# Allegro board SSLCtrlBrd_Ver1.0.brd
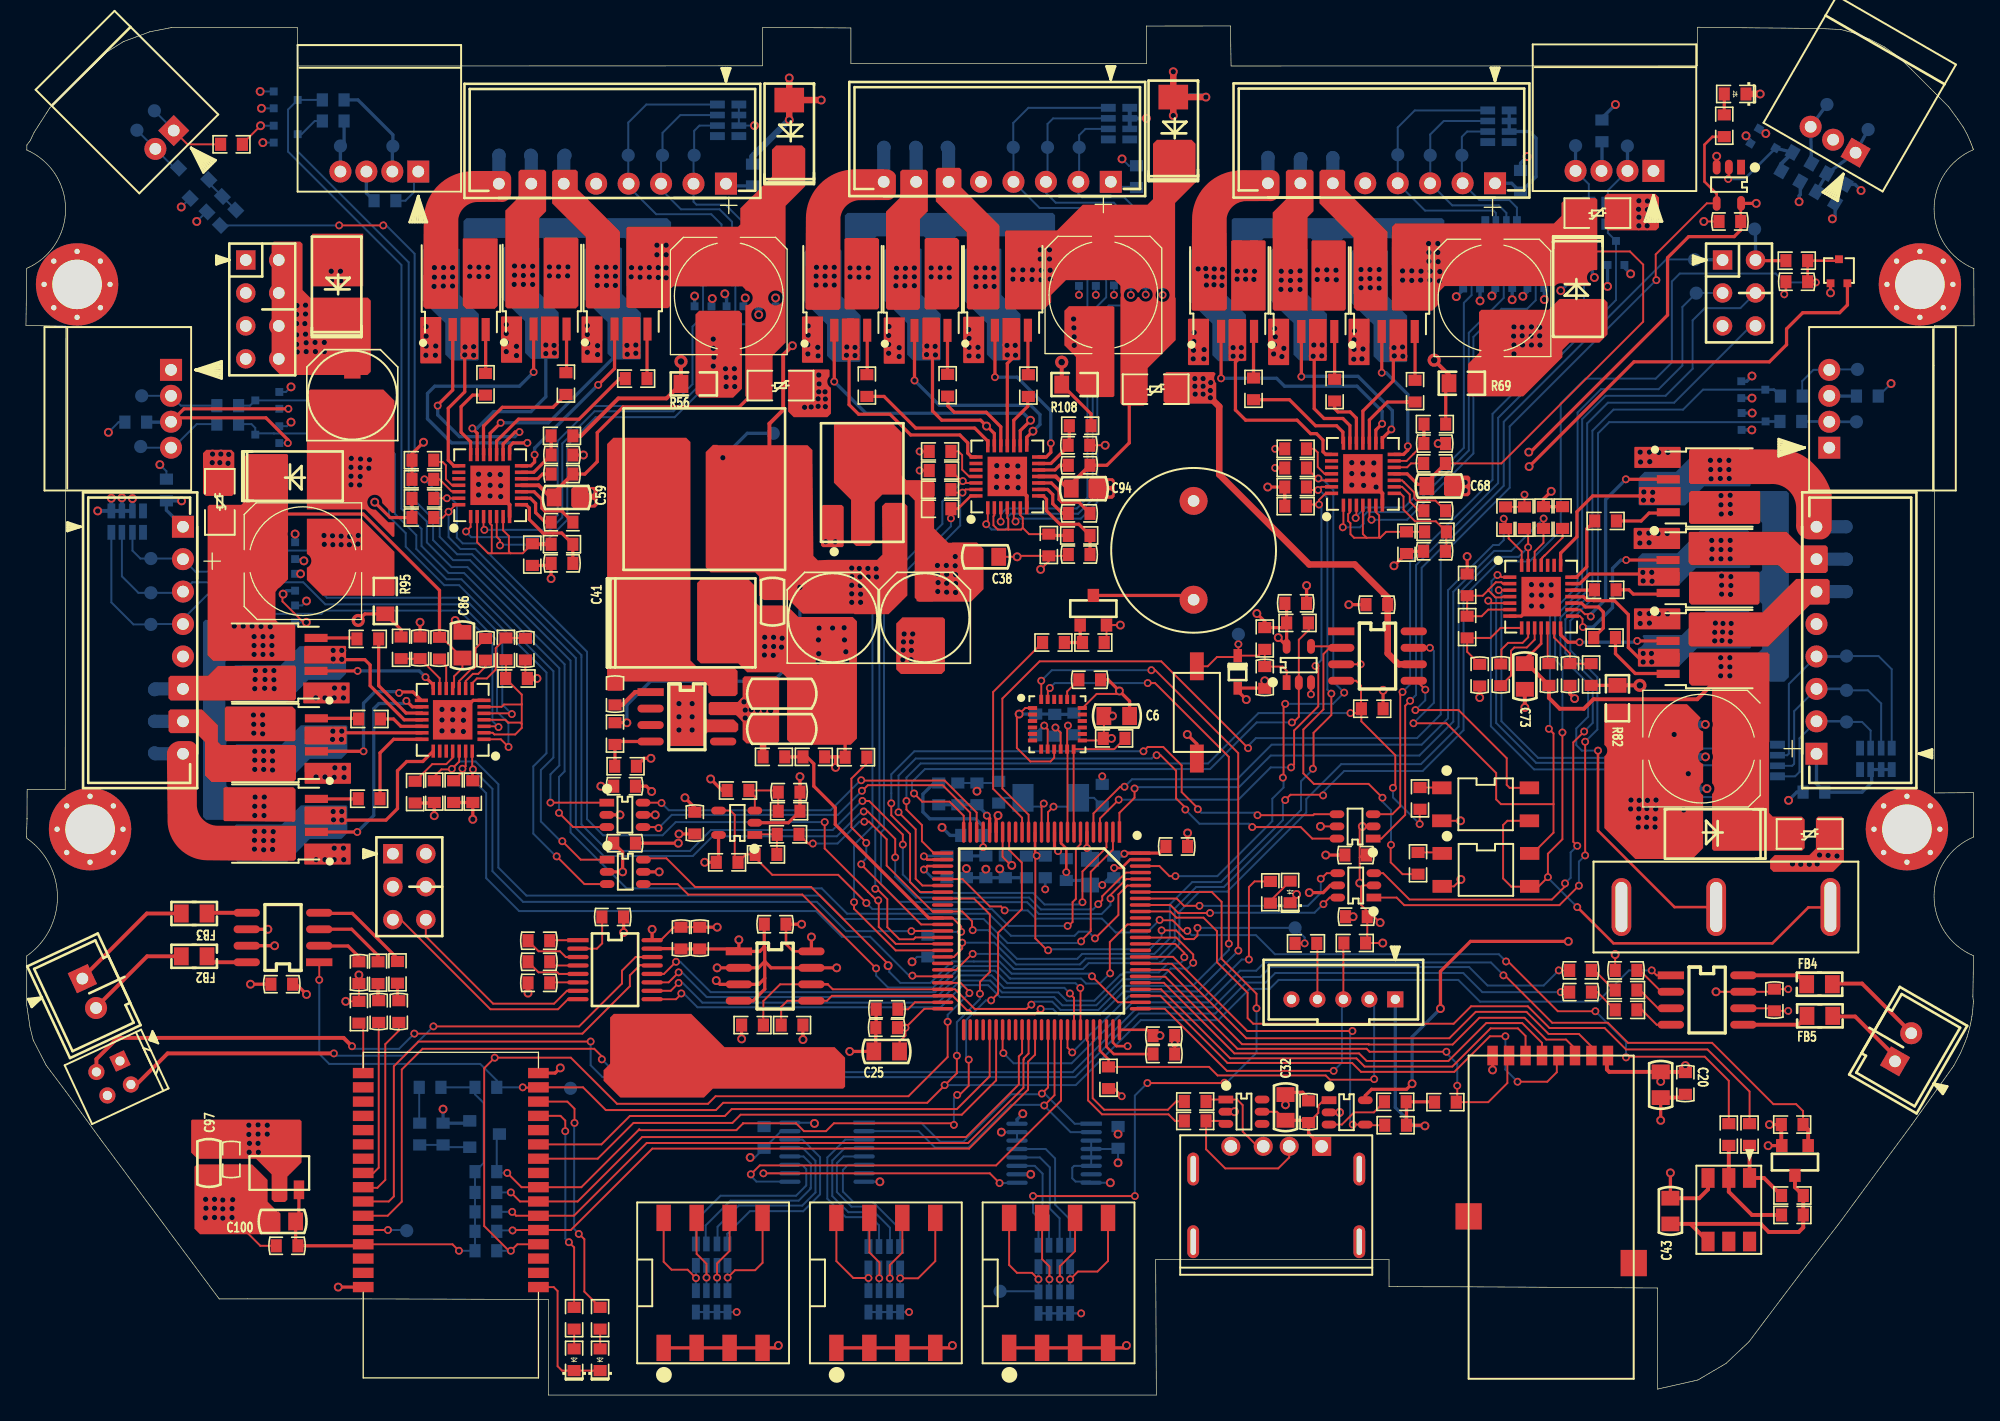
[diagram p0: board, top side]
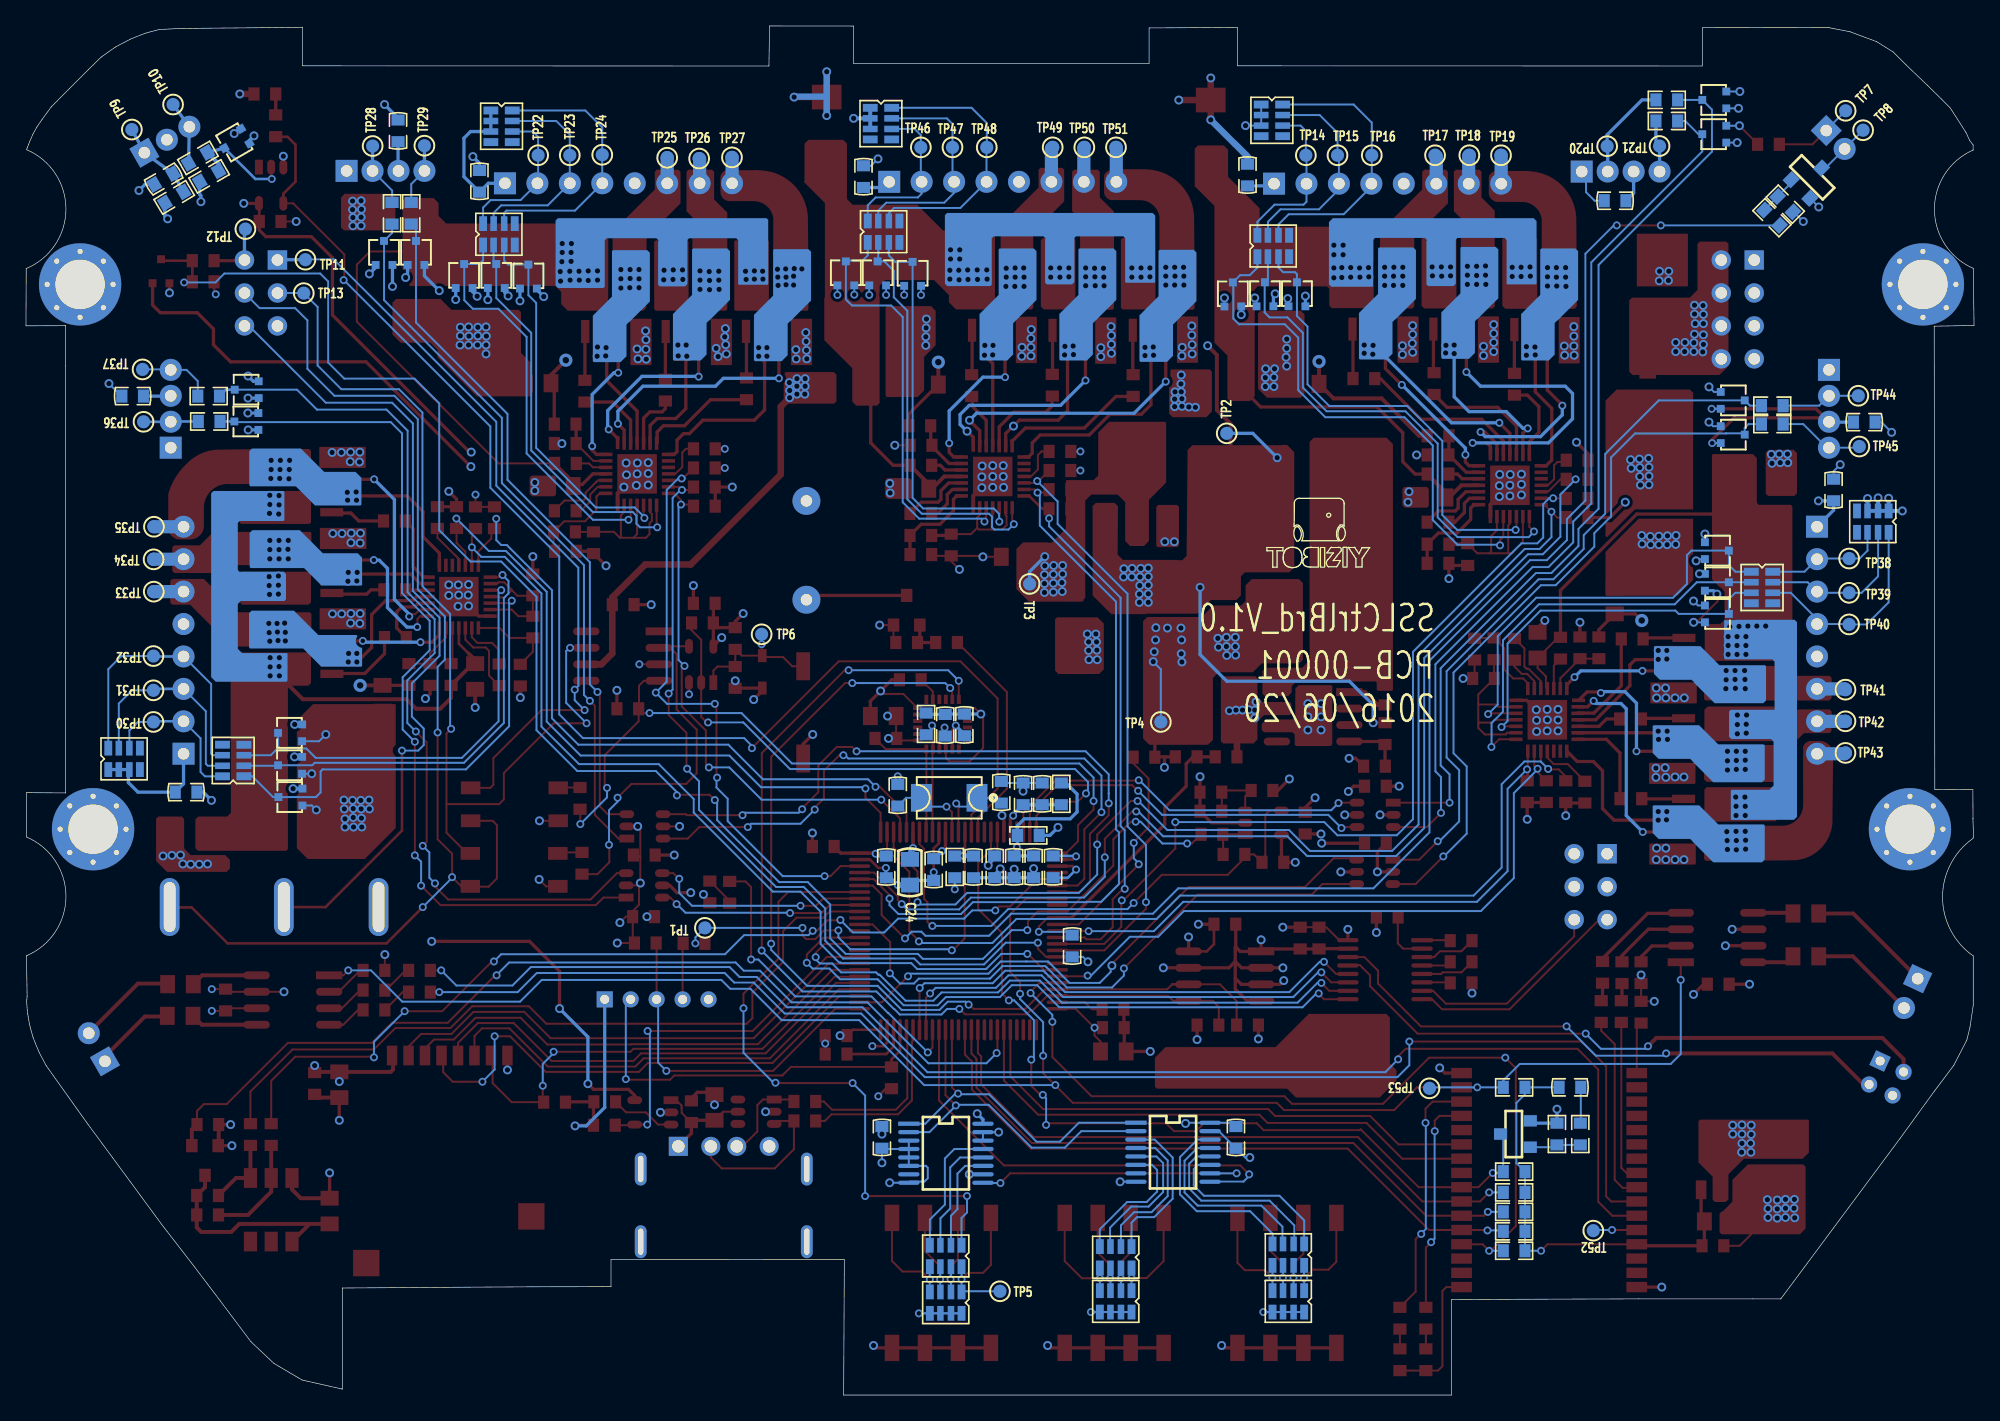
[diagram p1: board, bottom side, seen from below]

Outline 150.11 x 105.55 mm; copper layers: TOP, GND, POWER, BOTTOM. Coordinates in mm from the lower left corner of the outline.
Outline path: 0,82.46 0.06,86.86 arc(3.05,91.42) 0.07,95.98 0.07,96.01 0.07,96.37 0.33,96.71 0.63,97.35 1.83,99.22 2.5,99.9 3.59,100.97 5.23,102.54 6.23,103.54 7.51,104.34 9.55,105.1 11.19,105.42 20.91,105.44 20.94,102.46 56.75,102.48 56.77,105.44 63.57,105.4 63.57,102.65 86.35,102.65 86.33,105.54 92.81,105.55 92.86,102.46 128.79,102.48 128.79,105.45 138.31,105.35 139.85,105.27 140.93,104.98 142.04,104.54 143.22,103.92 144.31,103.15 145.3,102.18 146.77,100.71 148.16,99.31 148.86,98.35 149.28,97.74 149.58,97.19 149.83,96.62 149.91,96.41 149.99,96.21 150.03,96.1 150.06,96.01 arc(147.03,91.42) 150.09,86.84 150.09,86.83 150.11,82.43 147.06,82.44 147.06,82.42 147.05,79.34 147.06,46.42 150.07,46.44 150.07,43.02 arc(147.03,38.46) 150.03,33.88 150.07,33.86 150.02,30.71 150.06,30.35 150.01,29.67 149.97,29.37 149.94,29.16 149.9,28.94 149.85,28.65 149.78,28.36 149.7,28.04 149.57,27.6 149.4,27.15 149.08,26.39 148.55,25.39 145.33,20.87 143.44,18.31 139.67,13.18 137.12,9.88 135.13,7.25 132.77,4.11 131,2.44 128.83,1.16 125.77,0.47 125.73,0.46 125.73,8.26 111.09,8.35 105.67,8.36 105.03,8.36 105.03,10.45 87.05,10.44 87.1,0 40.26,0 40.26,7.37 25.86,7.42 14.9,7.42 14.89,7.41 5.71,19.77 3.07,23.41 1.56,25.42 0.56,27.36 0.31,28.37 0.06,30.06 0.06,33.85 arc(2.43,38.38) 0.08,42.91 0.04,43.05 0.09,44.43 0.08,44.42 0.09,46.68 3.02,46.7 3.07,82.4 0,82.46

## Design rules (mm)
net group O2: nets N16216872 N16216974 N16217240
net group O3: nets +5V GND_OPT N16214506

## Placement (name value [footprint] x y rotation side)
C1  18pF  [0603_C]  82.93 46.25 270 bottom
C2  18pF  [0603_C]  74.95 46.47 270 bottom
C3  0.1uF  [0603_C]  57.73 36.3 180 top
C4  0.1uF  [0603_C]  77.8 51.66 90 bottom
C5  0.1uF  [0603_C]  88.67 42.29 0 top
C6  10uF  [0805_C]  84.05 52.35 0 top
C7  0.1uF  [0603_C]  79.28 51.64 90 bottom
C8  2.2nF  [0603_C]  81.97 55.14 0 top
C9  2.2uF  [0603_C]  71.81 46.35 90 bottom
C10  0.1uF  [0603_C]  73.28 46.35 90 bottom
C11  0.1uF  [0603_C]  39.52 35.03 180 top
C12  0.1uF  [0603_C]  50.47 35.23 270 top
C13  2.2uF  [0603_C]  73.96 40.72 270 bottom
C14  0.1uF  [0603_C]  72.46 40.72 270 bottom
C15  0.1uF  [0603_C]  45.21 36.86 0 top
C16  4.7uF  [0603_C]  51.92 35.23 270 top
C17  0.1uF  [0603_C]  39.52 33.4 180 top
C18  0.1uF  [0603_C]  77.09 40.72 270 bottom
C19  0.1uF  [0603_C]  39.52 31.78 180 top
C20  10uF  [0805_C]  125.96 23.92 270 top
C21  0.1uF  [0603_C]  127.86 24.02 270 top
C22  2.2uF  [0603_C]  87.68 26.29 0 top
C23  2.2uF  [0603_C]  66.35 29.74 180 top
C24  10uF  [0805_C]  81.99 40.31 270 bottom
C25  10uF  [0805_C]  66.32 26.49 180 top
C26  0.1uF  [0603_C]  66.32 28.32 180 top
C27  0.1uF  [0603_C]  83.82 40.72 270 bottom
C28  0.1uF  [0603_C]  80.16 40.51 270 bottom
C29  0.1uF  [0603_C]  75.46 40.72 270 bottom
C30  0.1uF  [0603_C]  70.96 40.72 90 bottom
C31  0.1uF  [0603_C]  87.68 27.71 0 top
C32  10uF  [0805_C]  97.06 22.17 90 top
C33  0.1uF  [0603_C]  98.83 21.84 90 top
C34  0.01uF  [0603_C]  45.39 54.04 270 top
C35  100uF/35V  [CAP_E_SMD_250]  25.15 77.09 270 top
C36  10uF/35V  [1206_C]  58.24 54.07 0 top
C37  10uF/35V  [1206_C]  58.24 51.35 0 top
C38  10uF  [0805_C]  73.96 64.62 0 top
C39  220uF/10V  [CAP_E_SMD_250]  69.26 59.92 270 top
C40  220uF/10V  [CAP_E_SMD_250]  62.16 59.92 270 top
C41  22uF/10V  [0805_C]  57.53 61.18 270 top
C42  0.1uF  [0603_C]  56.87 19.86 270 bottom
C43  22uF/10V  [0805_C]  126.71 14.19 90 top
C44  0.1uF  [0603_C]  84.15 19.86 270 bottom
C45  0.1uF  [0603_C]  97.84 61.04 0 top
C46  0.1uF  [0603_C]  95.46 55.33 270 top
C47  2.2uF  [0603_C]  104.09 60.93 180 top
C48  0.1uF  [0603_C]  51.54 44.09 90 top
C49  0.1uF  [0603_C]  58.8 46.48 0 top
C50  4.7uF  [0603_C]  139.5 93.75 330 bottom
C51  0.1uF  [0603_C]  131.29 90.47 180 top
C52  0.1uF  [0603_C]  69.5 34.62 270 bottom
C53  0.1uF  [0603_C]  136.45 85.83 180 top
C54  0.1uF  [0603_C]  41.3 67.29 180 top
C55  0.1uF  [0603_C]  41.3 71 0 top
C56  0.1uF  [0603_C]  55.98 94.06 270 bottom
C57  0.1uF  [0603_C]  41.3 64.12 0 top
C58  220uF/35V  [CAP_E_SMD_315]  54.15 84.73 270 top
C59  4.7uF/35V  [0805_C]  41.68 69.2 180 top
C60  NOP  [0603_C]  41.3 72.48 180 top
C61  4.7uF  [0603_C]  27.66 92.08 180 bottom
C62  0.1uF  [0603_C]  46.13 46.94 0 top
C63  0.1uF  [0603_C]  108.55 68.17 180 top
C64  0.1uF  [0603_C]  108.54 71.82 0 top
C65  0.1uF  [0603_C]  115.17 93.57 270 bottom
C66  0.1uF  [0603_C]  108.54 65.05 0 top
C67  220uF/35V  [CAP_E_SMD_315]  113.01 84.58 270 top
C68  4.7uF/35V  [0805_C]  108.94 70.08 180 top
C69  NOP  [0603_C]  108.55 73.35 180 top
C70  4.7uF  [0603_C]  121.44 97.46 270 bottom
C71  0.1uF  [0603_C]  102.47 41.63 180 top
C72  0.1uF  [0603_C]  112.02 55.5 90 top
C73  4.7uF/35V  [0805_C]  115.5 55.4 90 top
C74  0.1uF  [0603_C]  113.64 55.52 90 top
C75  0.1uF  [0603_C]  117.35 55.55 270 top
C76  0.1uF  [0603_C]  137.77 46.48 0 bottom
C77  220uF/35V  [CAP_E_SMD_315]  129.11 49.83 180 top
C78  NOP  [0603_C]  118.98 55.55 90 top
C79  4.7uF  [0603_C]  141.89 77.01 180 bottom
C80  0.1uF  [0603_C]  102.52 36.88 180 top
C81  0.1uF  [0603_C]  35.41 57.49 270 top
C82  0.1uF  [0603_C]  31.87 57.58 90 top
C83  0.1uF  [0603_C]  10.82 69.77 270 bottom
C84  0.1uF  [0603_C]  38.48 57.51 90 top
C85  220uF/35V  [CAP_E_SMD_315]  21.34 64.29 0 top
C86  4.7uF/35V  [0805_C]  33.63 57.81 270 top
C87  NOP  [0603_C]  30.37 57.61 270 top
C88  4.7uF  [0603_C]  8.46 75.01 0 bottom
C89  0.1uF  [0603_C]  46.13 42.55 0 top
C90  0.1uF  [0603_C]  81.15 67.97 180 top
C91  0.1uF  [0603_C]  81.15 64.8 0 top
C92  0.1uF  [0603_C]  81.15 71.68 0 top
C93  220uF/35V  [CAP_E_SMD_315]  83.02 84.81 270 top
C94  4.7uF/35V  [0805_C]  81.54 69.88 180 top
C95  4.7uF  [0603_C]  85.57 93.93 270 bottom
C96  NOP  [0603_C]  81.14 73.22 180 top
C97  10uF  [0805_C]  14.1 17.91 270 top
C98  0.1uF  [0603_C]  15.83 18.16 90 top
C99  0.1uF  [0603_C]  20.12 11.51 0 top
C100  10uF  [0805_C]  19.79 13.39 180 top
C101  1uF  [0603_C]  25.66 32.56 270 top
C102  0.1uF  [0603_C]  27.18 29.57 90 top
C103  0.1uF  [0603_C]  28.73 29.57 90 top
C104  1uF  [0603_C]  19.71 31.67 0 top
C105  1uF  [0603_C]  31.14 23.72 180 bottom
C106  1uF  [0603_C]  123.29 32.74 180 top
C107  0.1uF  [0603_C]  119.79 32.74 0 top
C108  0.1uF  [0603_C]  119.79 31.06 0 top
C109  1uF  [0603_C]  134.72 30.45 270 top
D1  SMBJ18A  [SMB]  23.94 85.62 270 top
D2  B540C  [SMC]  50.75 59.53 180 top
D3  LED  [0603_LED]  97.41 38.79 270 top
D4  PESD3V3L1UA  [SOD-323]  93.37 55.75 90 top
D5  BAV99W  [SC70]  134.01 96.6 240 bottom
D6  LED  [0603_LED]  131.7 100.3 0 top
D7  BAV99W  [SC70]  139.7 86.64 180 top
D8  SMBJ18A  [SMB]  58.82 97.42 270 top
D9  BAV99W  [SC70]  57.11 84.85 0 bottom
D10  BAV99W  [SC70]  54.64 84.86 0 bottom
D11  BAV99W  [SC70]  52.17 84.86 0 bottom
D12  BAV99W  [SC70]  20.02 99.85 270 bottom
D13  BAV99W  [SC70]  20.02 97.21 270 bottom
D14  BAV99W  [SC70]  111.39 86.23 0 bottom
D15  BAV99W  [SC70]  116.35 86.27 0 bottom
D16  BAV99W  [SC70]  113.87 86.27 0 bottom
D17  SMBJ18A  [SMB]  119.59 85.27 90 top
D18  BAV99W  [SC70]  122.52 88.05 0 bottom
D19  BAV99W  [SC70]  120.06 88.05 0 bottom
D20  BAV99W  [SC70]  129.76 51.05 270 bottom
D21  BAV99W  [SC70]  129.73 46.1 270 bottom
D22  SMBJ18A  [SMB]  129.97 43.26 0 top
D23  BAV99W  [SC70]  129.76 48.55 270 bottom
D24  BAV99W  [SC70]  133.12 75.06 270 bottom
D25  BAV99W  [SC70]  133.1 77.51 270 bottom
D26  SMBJ18A  [SMB]  20.73 70.84 180 top
D27  BAV99W  [SC70]  19.81 65.1 90 bottom
D28  BAV99W  [SC70]  19.81 62.66 90 bottom
D29  BAV99W  [SC70]  19.81 60.22 90 bottom
D30  BAV99W  [SC70]  18.59 76.68 90 bottom
D31  BAV99W  [SC70]  18.59 74.04 90 bottom
D32  SMBJ18A  [SMB]  88.41 97.65 270 top
D33  BAV99W  [SC70]  86.93 86.47 0 bottom
D34  BAV99W  [SC70]  84.48 86.47 0 bottom
D35  BAV99W  [SC70]  81.79 86.44 0 bottom
D36  LED  [0603_LED]  44.24 2.72 270 top
D37  LED  [0603_LED]  42.24 2.72 270 top
FB1  100ohm  [0603_L]  72.87 43.15 0 bottom
FB2  600ohm/0.8A  [0805_L]  12.96 33.83 180 top
FB3  600ohm/0.8A  [0805_L]  12.96 37.13 180 top
FB4  600ohm/0.8A  [0805_L]  138.2 31.67 0 top
FB5  600ohm/0.8A  [0805_L]  138.23 29.24 0 top
H1  HOLE  [HOLE_3]  3.94 85.62 0 top
H2  HOLE  [HOLE_3]  145.94 85.62 0 top
H3  HOLE  [HOLE_3]  144.94 43.62 0 top
H4  HOLE  [HOLE_3]  4.94 43.62 0 top
J1  HEADER 5  [HDR200MS-1X5]  105.51 30.51 180 top
J2  HEADER 4  [HDR200MS-2X2]  7.24 25.76 295 top
J3  HEADER 8  [E01-ML01SP2]  111.17 26.17 270 top
J4  HEADER 4X2  [HDR254M-2X4]  16.94 87.5 270 top
J5  NOP  [SW3]  90.22 49.07 90 top
J6  HEADER 3X2  [HDR254M-2X3]  28.27 41.73 270 top
J7  HEADER 2  [HY200-WF_1X2]  7.85 99.61 225 top
J8  HEADER 3  [HY200-WF_1X3]  141.25 100.24 150 top
J9  HEADER 3X2  [HDR254M-2X3]  130.73 87.5 270 top
J10  HEADER 8  [HA250-AW-1X8]  53.94 95.34 180 top
J11  HEADER 4  [HY200-WF_1X4]  27.23 98.32 180 top
J12  HEADER 8  [HA250-AW-1X8]  113.2 95.37 180 top
J13  HEADER 4  [HY200-WF_1X4]  122.4 98.37 180 top
J14  HEADER 4  [HY200-WF_1X4]  142.95 76.03 90 top
J15  HEADER 8  [HA250-AW-1X8]  10.15 66.94 270 top
J16  HEADER 4  [HY200-WF_1X4]  7.18 76.03 270 top
J17  HEADER 8  [HA250-AW-1X8]  83.59 95.48 180 top
J18  SPEAKE  [HDR250MS-1X2]  4.35 32.11 295 top
J19  SPEAKE  [HDR250MS-1X2]  144.02 25.73 60 top
J20  HEADER 8  [HA250-AW-1X8]  139.92 49.44 90 top
L1  22uH/4A  [L_12MMX12MM]  52.27 69.84 180 top
LS1  SPEAKER  [BEEP_500MIL]  89.46 65.12 270 top
Q1  MMBT3904  [SOT23]  82.25 60.5 0 top
Q2  CES2301  [SOT23]  136.31 18.09 180 top
Q3  CES2302  [SOT23]  12.56 93.79 225 bottom
Q4  AON6884  [PWRPAK_SO8_DUAL]  33.52 85.19 90 top
Q5  AON6884  [PWRPAK_SO8_DUAL]  39.75 85.23 90 top
Q6  AON6884  [PWRPAK_SO8_DUAL]  45.99 85.23 90 top
Q7  AON6884  [PWRPAK_SO8_DUAL]  92.72 85.05 90 top
Q8  AON6884  [PWRPAK_SO8_DUAL]  98.91 85.04 90 top
Q9  AON6884  [PWRPAK_SO8_DUAL]  105.11 85.04 90 top
Q10  AON6884  [PWRPAK_SO8_DUAL]  129.6 69.96 0 top
Q11  AON6884  [PWRPAK_SO8_DUAL]  129.59 63.74 0 top
Q12  AON6884  [PWRPAK_SO8_DUAL]  129.59 57.51 0 top
Q13  AON6884  [PWRPAK_SO8_DUAL]  19.33 44.06 180 top
Q14  AON6884  [PWRPAK_SO8_DUAL]  19.33 50.27 180 top
Q15  AON6884  [PWRPAK_SO8_DUAL]  19.31 56.46 180 top
Q16  AON6884  [PWRPAK_SO8_DUAL]  62.92 85.14 90 top
Q17  AON6884  [PWRPAK_SO8_DUAL]  69.1 85.13 90 top
Q18  AON6884  [PWRPAK_SO8_DUAL]  75.3 85.14 90 top
Q19  MMBT3904  [SOT23]  35.34 20.12 90 bottom
R1  3.3K  [0603_R]  55.98 28.52 180 top
R2  3.3K  [0603_R]  59.03 28.52 0 top
R3  5.1K  [0603_R]  80.75 51.74 270 bottom
R4  5.1K  [0603_R]  83.85 50.62 0 top
R5  10K  [0603_R]  83.42 24.46 90 top
R6  10K  [0603_R]  102.39 34.85 180 top
R7  0R  [0603_R]  98.63 34.82 180 top
R8  2.2K  [0603_R]  79.17 58.01 0 top
R9  1K  [0603_R]  82.25 58.01 180 top
R10  22R  [0603_R]  70.33 46.35 90 bottom
R11  10K  [0603_R]  78.54 40.72 90 bottom
R12  10K  [0603_R]  109.37 22.58 180 top
R13  5.1K  [0603_R]  63.96 49.17 180 top
R14  10K  [0603_R]  105.54 20.8 180 top
R15  10K  [0603_R]  105.51 22.61 180 top
R16  22R  [0603_R]  90.1 21.13 0 top
R17  22R  [0603_R]  90.1 22.63 0 top
R18  10K  [0603_R]  45.39 50.99 270 top
R19  3.24K  [0603_R]  46.2 48.48 0 top
R20  4.99K  [0603_R]  136.11 15.39 180 top
R21  4.99K  [0603_R]  136.11 13.89 180 top
R22  1K  [0603_R]  132.81 20.09 90 top
R23  680R  [0603_R]  95.89 38.76 90 top
R24  1K  [0603_R]  131.21 20.09 90 top
R25  10K  [0603_R]  136.1 20.85 0 top
R26  1K  [0603_R]  107.27 41 270 top
R27  1K  [0603_R]  107.42 46 270 top
R28  10K  [0603_R]  95.46 58.33 90 top
R29  10K  [0603_R]  97.98 59.53 180 top
R30  300R  [0603_R]  15.84 96.42 0 top
R31  5.1K  [0603_R]  103.74 52.91 180 top
R32  100R  [0603_R]  15.57 90.77 45 bottom
R33  3.3K  [0603_R]  14.54 91.81 45 bottom
R34  100K  [0603_R]  57.03 41.68 180 top
R35  10K  [0603_R]  135.99 93.95 330 bottom
R36  100R  [0603_R]  138.69 92.33 329.1 bottom
R37  1K  [0603_R]  58.73 43.23 180 top
R38  5.1K  [0603_R]  54.03 41.07 180 top
R39  10K  [0603_R]  54.87 46.61 0 top
R40  1K  [0603_R]  136.86 95.38 330 bottom
R41  1.5K  [0603_R]  58.8 45.01 180 top
R42  680R  [0603_R]  130.86 97.85 270 top
R43  22K  [0603_R]  57.63 49.2 0 top
R44  1K  [0603_R]  136.45 87.45 0 top
R45  3.3K  [0603_R]  60.71 49.2 180 top
R46  0R  [0603_R]  30.58 72.07 0 top
R47  10R  [0603_R]  35.41 77.93 90 top
R48  5.1K  [0603_R]  39.02 64.8 90 top
R49  10K  [0603_R]  41.3 65.59 0 top
R50  10R  [0603_R]  41.61 77.98 90 top
R51  10R  [0603_R]  47.02 78.36 0 top
R52  0R  [0603_R]  41.3 73.95 0 top
R53  5.1K  [0603_R]  30.58 70.6 0 top
R54  5.1K  [0603_R]  30.58 69.12 0 top
R55  5.1K  [0603_R]  30.58 67.65 0 top
R56  51mR  [0805_R]  51.46 77.95 180 top
R57  330R  [0603_R]  23.68 99.85 0 bottom
R58  330R  [0603_R]  23.68 98.22 0 bottom
R59  0R  [0603_R]  97.84 72.95 0 top
R60  10R  [0603_R]  94.59 77.57 90 top
R61  5.1K  [0603_R]  106.38 65.71 90 top
R62  10K  [0603_R]  108.61 66.55 0 top
R63  10R  [0603_R]  100.84 77.47 90 top
R64  10R  [0603_R]  107.04 77.39 90 top
R65  5.1K  [0603_R]  97.84 71.47 0 top
R66  5.1K  [0603_R]  97.84 70 0 top
R67  5.1K  [0603_R]  97.84 68.53 0 top
R68  0R  [0603_R]  108.56 74.85 0 top
R69  51mR  [0805_R]  110.64 78 180 top
R70  330R  [0603_R]  121.9 91.11 90 bottom
R71  330R  [0603_R]  120.42 91.11 90 bottom
R72  0R  [0603_R]  118.4 67.65 270 top
R73  10R  [0603_R]  121.72 67.39 0 top
R74  5.1K  [0603_R]  111.05 62.46 270 top
R75  10K  [0603_R]  111.05 59.21 270 top
R76  10R  [0603_R]  121.69 62.08 0 top
R77  10R  [0603_R]  121.64 58.39 0 top
R78  5.1K  [0603_R]  116.93 67.65 270 top
R79  5.1K  [0603_R]  115.47 67.64 270 top
R80  5.1K  [0603_R]  114.01 67.64 270 top
R81  0R  [0603_R]  120.6 55.55 270 top
R82  51mR  [0805_R]  122.63 53.72 90 top
R83  330R  [0603_R]  135.99 75.06 0 bottom
R84  330R  [0603_R]  136.03 77.01 0 bottom
R85  0R  [0603_R]  29.99 46.48 90 top
R86  10R  [0603_R]  26.44 45.97 180 top
R87  5.1K  [0603_R]  37.8 55.25 180 top
R88  10K  [0603_R]  36.98 57.53 90 top
R89  10R  [0603_R]  26.47 52.12 180 top
R90  10R  [0603_R]  26.34 58.29 180 top
R91  5.1K  [0603_R]  31.46 46.52 90 top
R92  5.1K  [0603_R]  32.96 46.52 90 top
R93  5.1K  [0603_R]  34.43 46.52 90 top
R94  0R  [0603_R]  28.91 57.61 90 top
R95  51mR  [0805_R]  27.69 61.21 270 top
R96  330R  [0603_R]  15.55 76.28 180 bottom
R97  330R  [0603_R]  15.55 74.85 180 bottom
R98  0R  [0603_R]  70.44 72.75 0 top
R99  10R  [0603_R]  64.8 77.83 90 top
R100  5.1K  [0603_R]  78.82 65.53 90 top
R101  10K  [0603_R]  81.15 66.27 0 top
R102  10R  [0603_R]  71.02 77.85 90 top
R103  10R  [0603_R]  77.24 77.82 90 top
R104  5.1K  [0603_R]  70.44 71.27 0 top
R105  5.1K  [0603_R]  70.44 69.8 0 top
R106  0R  [0603_R]  81.23 74.73 0 top
R107  5.1K  [0603_R]  70.44 68.33 0 top
R108  51mR  [0805_R]  80.8 77.9 180 top
R109  1K  [0603_R]  35.44 11.12 180 bottom
R110  1K  [0603_R]  35.44 12.62 180 bottom
R111  1K  [0603_R]  35.44 14.12 180 bottom
R112  1K  [0603_R]  35.44 15.62 180 bottom
R113  0R  [0603_R]  35.44 23.72 180 bottom
R114  1K  [0603_R]  44.24 5.92 270 top
R115  1K  [0603_R]  42.24 5.92 270 top
R116  0R  [0603_R]  25.66 29.51 90 top
R117  12K  [0603_R]  27.13 32.56 90 top
R118  12K  [0603_R]  28.63 32.59 90 top
R119  10K  [0603_R]  35.44 17.22 180 bottom
R120  1K  [0603_R]  30.34 20.12 90 bottom
R121  12K  [0603_R]  123.29 31.22 0 top
R122  10K  [0603_R]  32.14 20.12 270 bottom
R123  12K  [0603_R]  123.29 29.69 0 top
RP1  1K  [0603_8P4R]  52.84 10.82 270 bottom
RP2  5.1K  [0603_8P4R]  52.84 7.22 270 bottom
RP3  1K  [0603_8P4R]  66.14 10.62 270 bottom
RP4  5.1K  [0603_8P4R]  66.14 7.22 270 bottom
RP5  1K  [0603_8P4R]  79.24 10.72 270 bottom
RP6  5.1K  [0603_8P4R]  79.24 7.12 270 bottom
RP7  5.1K  [0603_8P4R]  54.1 98.27 180 bottom
RP8  330R  [0603_8P4R]  54 88.58 90 bottom
RP9  5.1K  [0603_8P4R]  113.46 97.82 180 bottom
RP10  330R  [0603_8P4R]  113.67 89.48 90 bottom
RP11  5.1K  [0603_8P4R]  142.55 49.05 90 bottom
RP12  330R  [0603_8P4R]  134.14 48.92 0 bottom
RP13  5.1K  [0603_8P4R]  7.8 67.34 270 bottom
RP14  330R  [0603_8P4R]  16.33 62.26 180 bottom
RP15  5.1K  [0603_8P4R]  84.23 98.02 180 bottom
RP16  330R  [0603_8P4R]  84.03 89.69 90 bottom
TP1  TP  [TP6]  97.79 36.02 180 bottom
TP2  TP  [TP6]  57.58 74.14 180 bottom
TP3  TP  [TP6]  72.77 62.53 0 bottom
TP4  TP  [TP6]  62.66 51.89 180 bottom
TP5  TP  [TP6]  75.06 8 180 bottom
TP6  TP  [TP6]  93.42 58.65 180 bottom
TP7  TP  [TP6]  9.9 99.01 180 bottom
TP8  TP  [TP6]  8.55 97.51 180 bottom
TP9  TP  [TP6]  141.95 97.56 180 bottom
TP10  TP  [TP6]  138.78 99.49 180 bottom
TP11  TP  [TP6]  128.58 87.53 180 bottom
TP12  TP  [TP6]  133.2 89.89 180 bottom
TP13  TP  [TP6]  128.7 84.95 180 bottom
TP14  TP  [TP6]  51.49 95.58 180 bottom
TP15  TP  [TP6]  49.05 95.58 180 bottom
TP16  TP  [TP6]  46.41 95.58 180 bottom
TP17  TP  [TP6]  41.53 95.58 180 bottom
TP18  TP  [TP6]  38.89 95.58 180 bottom
TP19  TP  [TP6]  36.45 95.58 180 bottom
TP20  TP  [TP6]  28.27 96.28 180 bottom
TP21  TP  [TP6]  24.23 96.29 180 bottom
TP22  TP  [TP6]  110.64 95.58 180 bottom
TP23  TP  [TP6]  108.21 95.58 180 bottom
TP24  TP  [TP6]  105.7 95.62 180 bottom
TP25  TP  [TP6]  100.7 95.39 180 bottom
TP26  TP  [TP6]  98.24 95.33 180 bottom
TP27  TP  [TP6]  95.71 95.41 180 bottom
TP28  TP  [TP6]  123.4 96.29 180 bottom
TP29  TP  [TP6]  119.41 96.32 180 bottom
TP30  TP  [TP6]  140.29 51.89 180 bottom
TP31  TP  [TP6]  140.29 54.33 180 bottom
TP32  TP  [TP6]  140.29 56.97 180 bottom
TP33  TP  [TP6]  140.26 61.94 180 bottom
TP34  TP  [TP6]  140.27 64.43 180 bottom
TP35  TP  [TP6]  140.25 66.94 180 bottom
TP36  TP  [TP6]  141.05 75.03 180 bottom
TP37  TP  [TP6]  141.12 79.07 180 bottom
TP38  TP  [TP6]  9.63 64.49 180 bottom
TP39  TP  [TP6]  9.63 61.85 180 bottom
TP40  TP  [TP6]  9.63 59.41 180 bottom
TP41  TP  [TP6]  9.91 54.38 180 bottom
TP42  TP  [TP6]  9.91 51.94 180 bottom
TP43  TP  [TP6]  9.91 49.5 180 bottom
TP44  TP  [TP6]  8.92 77.04 180 bottom
TP45  TP  [TP6]  8.84 73.13 180 bottom
TP46  TP  [TP6]  81.16 96.19 180 bottom
TP47  TP  [TP6]  78.72 96.19 180 bottom
TP48  TP  [TP6]  76.08 96.19 180 bottom
TP49  TP  [TP6]  71 96.19 180 bottom
TP50  TP  [TP6]  68.56 96.19 180 bottom
TP51  TP  [TP6]  66.12 96.19 180 bottom
TP52  TP  [TP6]  29.34 12.67 180 bottom
TP53  TP  [TP6]  41.96 23.65 180 bottom
U1  STM32F407VET6  [TQFP100]  78.26 35.78 270 top
U2  24LC64  [SO-8]  57.73 32.3 0 top
U3  MPU-6050  [QFN24_157X157_197_NO_EP]  79.48 51.71 0 top
U4  SP3232E  [TSSOP-16]  45.39 32.79 0 top
U5  STMPS2141STR  [SOT23-5]  101.81 21.79 0 top
U6  USB_HOST  [USB_A_SHORT]  96.34 11.82 0 top
U7  PRTR5V0U4D  [SOT23-6]  93.86 21.84 0 top
U8  AMS1117-3.3  [SOT223]  64.57 70.35 90 top
U9  TPS5430  [SO-8-T-PAD]  50.93 52.29 0 top
U10  DIP_SW_4B  [DIP_SW_2_54_4P]  56.76 12.46 0 top
U11  74HC165  [TSSOP-16]  61.72 18.72 180 bottom
U12  DIP_SW_4B  [DIP_SW_2_54_4P]  70.07 12.46 0 top
U13  74HC165  [TSSOP-16]  79.22 18.64 180 bottom
U14  APA102  [LED_5050]  131.21 14.29 270 top
U15  DIP_SW_4B  [DIP_SW_2_54_4P]  83.38 12.46 0 top
U16  EL357  [PC357]  112.5 40.49 0 top
U17  EL357  [PC357]  112.47 45.54 0 top
U18  SN74LVC1G00  [SOT23-5]  98.08 56.33 90 top
U19  NOP  [SO-8]  104.14 56.97 0 top
U20  LMV331  [SOT23-5]  54.76 44.12 180 top
U21  SN74LVC1G17  [SOT23-5]  131.22 93.27 270 top
U22  -  [SS-01GL13]  139.04 37.63 180 top
U23  A4931  [QFN28_197X197_197_EP]  35.77 70.14 90 top
U24  4A  [1206_F]  58.14 77.83 0 top
U25  SN74LVC2G17  [SOT23-6]  46.15 44.73 0 top
U26  A4931  [QFN28_197X197_197_EP]  103.02 71.02 90 top
U27  4A  [1206_F]  121.08 91.12 0 top
U28  SN74LVC2G17  [SOT23-6]  102.42 43.84 180 top
U29  A4931  [QFN28_197X197_197_EP]  116.75 61.55 0 top
U30  4A  [1206_F]  137.44 43.26 0 top
U31  SN74LVC2G17  [SOT23-6]  102.47 39.29 180 top
U32  A4931  [QFN28_197X197_197_EP]  32.88 52.06 180 top
U33  4A  [1206_F]  14.94 68.86 90 top
U34  SN74LVC2G17  [SOT23-6]  46.18 40.34 0 top
U35  A4931  [QFN28_197X197_197_EP]  75.62 70.82 90 top
U36  4A  [1206_F]  87.05 77.55 0 top
U37  HT7536  [SOT-89]  18.04 15.82 0 top
U38  -  [BK8000L]  32.74 16.02 180 top
U39  HT6872  [SO-8]  19.81 35.27 180 top
U40  HT6872  [SO-8]  129.54 30.45 0 top
Y1  25MHz  [OSCSC254P500X320X100-2]  78.97 46.04 0 bottom

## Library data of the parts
C1-C34 C36-C38 C41-C53 C61 C62 C70 C71 C79 C80 C88-C92 C94-C109 = CAP NP
C35 C39 C40 = CAP P
C54-C57 C59 C60 = CAP NP: room: M1
C58 = CAP P: User Part Number: CAPAE_315X405; room: M1
C63-C66 C68 C69 = CAP NP: room: M2
C67 = CAP P: User Part Number: CAPAE_315X405; room: M2
C72-C76 C78 = CAP NP: room: M3
C77 = CAP P: User Part Number: CAPAE_315X405; room: M3
C81-C84 C86 C87 = CAP NP: room: M4
C85 = CAP P: User Part Number: CAPAE_315X405; room: M4
C93 = CAP P: User Part Number: CAPAE_315X405
D1 D32 = ZENER
D2 = DIODE Schottky
D3 D6 D36 D37 = LED
D4 = ZENER: Tolerance: RichardLC; User Part Number: pn
D5 D7 D12 D13 D18 D19 D24 D25 D30 D31 D33-D35 = DIODE_2X_S_SOT23: Tolerance: RichardLC; User Part Number: pn
D8 = ZENER: room: M1
D9-D11 = DIODE_2X_S_SOT23: Tolerance: RichardLC; User Part Number: pn; room: M1
D14-D16 = DIODE_2X_S_SOT23: Tolerance: RichardLC; User Part Number: pn; room: M2
D17 = ZENER: room: M2
D20 D21 D23 = DIODE_2X_S_SOT23: Tolerance: RichardLC; User Part Number: pn; room: M3
D22 = ZENER: room: M3
D26 = ZENER: room: M4
D27-D29 = DIODE_2X_S_SOT23: Tolerance: RichardLC; User Part Number: pn; room: M4
FB1-FB5 = FB
H1-H4 = HOLE
J1 = HEADER 5: Tolerance: RichardLC; User Part Number: pn
J2 = HEADER 4
J3 = HEADER 8
J4 = HEADER 4X2: Tolerance: RichardLC; User Part Number: pn
J5 = SW_2
J6 J9 = HEADER 3X2: Tolerance: RichardLC; User Part Number: pn
J7 J18 J19 = HEADER 2: Tolerance: RichardLC; User Part Number: pn
J8 = HEADER 3: Tolerance: RichardLC; User Part Number: pn
J10 = HEADER 8: Tolerance: RichardLC; User Part Number: pn; room: M1
J11 J13 J14 J16 = HEADER 4: Tolerance: RichardLC; User Part Number: pn
J12 = HEADER 8: Tolerance: RichardLC; User Part Number: pn; room: M2
J15 J20 = HEADER 8: Tolerance: RichardLC; User Part Number: pn; room: M4
J17 = HEADER 8: Tolerance: RichardLC; User Part Number: pn
L1 = L_0
LS1 = SPEAKER
Q1 Q19 = NPN,SOT23
Q2 = PMOS,SOT23
Q3 = NMOS,SOT23
Q4-Q18 = AON6884: User Part Number: PWRPAK_SO8_DUAL_R2
R1-R45 R57 R58 R65 R70 R71 R83 R84 R96-R123 = RES_2
R46-R56 = RES_2: room: M1
R59-R64 R66-R69 = RES_2: room: M2
R72-R82 = RES_2: room: M3
R85-R95 = RES_2: room: M4
RP1-RP16 = RP_S
TP1-TP13 TP20 TP21 TP28 TP29 TP36 TP37 TP44-TP51 = TP
TP14-TP19 TP52 TP53 = TP: room: M1
TP22-TP27 = TP: room: M2
TP30-TP35 = TP: room: M3
TP38-TP43 = TP: room: M4
U1 = STM32F407VET6
U2 = 24LC64
U3 = MPU-6050: User Part Number: QFN24_157X157_197_EP
U4 = MAX3232CSE
U5 = STMPS2141STR
U6 = USB_HOST
U7 = AZC099-04S
U8 = AMS1117-5.0
U9 = TPS5450
U10 U12 U15 = DIP_SW_4B
U11 U13 = 74HC165
U14 = APA102
U16 U17 = PC357
U18 = SN74AHC1G00
U19 = MC34152D
U20 = LMV331
U21 = SN74LVC1G17
U22 = SW_7
U23 = A4931: User Part Number: QFN28_197X197_197_EP; room: M1
U24 = FUSE: room: M1
U25 U28 U31 U34 = SN74LVC2G17
U26 = A4931: User Part Number: QFN28_197X197_197_EP; room: M2
U27 = FUSE: room: M2
U29 = A4931: User Part Number: QFN28_197X197_197_EP; room: M3
U30 = FUSE: room: M3
U32 = A4931: User Part Number: QFN28_197X197_197_EP; room: M4
U33 = FUSE: room: M4
U35 = A4931: User Part Number: QFN28_197X197_197_EP
U36 = FUSE
U37 = HT7536
U38 = BK8000L
U39 U40 = HT6872
Y1 = XTAL: Tolerance: RichardLC; User Part Number: pn

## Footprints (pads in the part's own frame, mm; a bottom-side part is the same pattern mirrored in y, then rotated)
0603_8P4R
  rect 1.143x0.61 smd: 1(-0.826,1.219) 4(-0.826,-1.219) 5(0.826,-1.219) 8(0.826,1.219)
  rect 1.143x0.508 smd: 2(-0.826,0.406) 3(-0.826,-0.406) 6(0.826,-0.406) 7(0.826,0.406)
0603_C
  rect 0.864x1.016 smd: 1(-0.838,0) 2(0.838,0)
0603_L
  rect 0.864x1.016 smd: 1(-0.838,0) 2(0.838,0)
0603_LED
  rect 0.864x1.016 smd: 1(-0.838,0) 2(0.838,0)
0603_R
  rect 0.864x1.016 smd: 1(-0.838,0) 2(0.838,0)
0805_C
  rect 1.143x1.397 smd: 1(-0.991,0) 2(0.991,0)
0805_L
  rect 1.143x1.397 smd: 1(-0.991,0) 2(0.991,0)
0805_R
  rect 1.143x1.397 smd: 1(-0.991,0) 2(0.991,0)
1206_C
  rect 1.524x1.778 smd: 1(-1.524,0) 2(1.524,0)
1206_F
  rect 1.524x1.778 smd: 1(-1.524,0) 2(1.524,0)
BEEP_500MIL
  round 2.159 hole 0.889: 1(-3.81,0.508) 2(3.81,0.508)
BK8000L
  rect 1.6x0.8 smd: 1(-6.75,7.7) 2(-6.75,6.6) 3(-6.75,5.5) 4(-6.75,4.4) 5(-6.75,3.3) 6(-6.75,2.2) 7(-6.75,1.1) 8(-6.75,0) 9(-6.75,-1.1) 10(-6.75,-2.2) 11(-6.75,-3.3) 12(-6.75,-4.4) 13(-6.75,-5.5) 14(-6.75,-6.6) 15(-6.75,-7.7) 16(-6.75,-8.8) 17(6.75,-8.8) 18(6.75,-7.7) 19(6.75,-6.6) 20(6.75,-5.5) 21(6.75,-4.4) 22(6.75,-3.3) 23(6.75,-2.2) 24(6.75,-1.1) 25(6.75,0) 26(6.75,1.1) 27(6.75,2.2) 28(6.75,3.3) 29(6.75,4.4) 30(6.75,5.5) 31(6.75,6.6) 32(6.75,7.7)
CAP_E_SMD_250
  rect 2.794x1.27 smd: 1(-2.667,0) 2(2.667,0)
CAP_E_SMD_315
  rect 3.937x1.524 smd: 1(-3.124,0) 2(3.124,0)
DIP_SW_2_54_4P
  rect 1.118x2.032 smd: 1(-7.62,-8.82) 2(-5.08,-8.82) 3(-2.54,-8.82) 4(0,-8.82) 5(0,1.2) 6(-2.54,1.2) 7(-5.08,1.2) 8(-7.62,1.2)
E01-ML01SP2
  rect 2.032x2.032 smd: (12.4,0) (16,12.72)
  rect 1.524x0.813 smd: 1(0,10.735) 2(0,9.465) 3(0,8.195) 4(0,6.925) 5(0,5.655) 6(0,4.385) 7(0,3.115) 8(0,1.845)
HA250-AW-1X8
  rect 1.7x1.7 hole 0.9: 1(0,1.95)
  round 1.7 hole 0.9: 2(2.5,1.95) 3(5,1.95) 4(7.5,1.95) 5(10,1.95) 6(12.5,1.95) 7(15,1.95) 8(17.5,1.95)
HDR200MS-1X5
  rect 1.25x1.25 hole 0.7: 1(0,0)
  round 1.25 hole 0.7: 2(2,0) 3(4,0) 4(6,0) 5(8,0)
HDR200MS-2X2
  rect 1.25x1.25 hole 0.7: 1(0,0)
  round 1.25 hole 0.7: 2(2,0) 3(0,-2) 4(2,-2)
HDR250MS-1X2
  rect 1.7x1.7 hole 0.9: 1(0,0)
  round 1.7 hole 0.9: 2(2.5,0)
HDR254M-2X3
  rect 1.5x1.5 hole 0.9: 1(0,0)
  round 1.5 hole 0.9: 2(0,2.54) 3(2.54,0) 4(2.54,2.54) 5(5.08,0) 6(5.08,2.54)
HDR254M-2X4
  rect 1.5x1.5 hole 0.9: 1(0,0)
  round 1.5 hole 0.9: 2(0,2.54) 3(2.54,0) 4(2.54,2.54) 5(5.08,0) 6(5.08,2.54) 7(7.62,0) 8(7.62,2.54)
HOLE_3
  round 6.35 hole 3.81: 1(0,0)
  round 0.762 hole 0.406: 2(2.54,0) 3(1.796,1.796) 4(0,2.54) 5(-1.796,1.796) 6(-2.54,0) 7(-1.796,-1.796) 8(0,-2.54) 9(1.796,-1.796)
HY200-WF_1X2
  rect 1.7x1.7 hole 0.9: 1(-1,4)
  round 1.7 hole 0.9: 2(1,4)
HY200-WF_1X3
  rect 1.7x1.7 hole 0.9: 1(-2,4)
  round 1.7 hole 0.9: 2(0,4) 3(2,4)
HY200-WF_1X4
  rect 1.7x1.7 hole 0.9: 1(-3,4)
  round 1.7 hole 0.9: 2(-1,4) 3(1,4) 4(3,4)
L_12MMX12MM
  rect 4.572x5.842 smd: 1(-5.016,0) 2(5.016,0)
LED_5050
  rect 1.524x1.016 smd: 1(-2.45,1.6) 2(-2.45,0) 3(-2.45,-1.6) 4(2.45,-1.6) 5(2.45,0) 6(2.45,1.6)
OSCSC254P500X320X100-2
  rect 1.62x2.14 smd: 1(-2.14,0) 2(2.14,0)
PC357
  rect 1.499x0.991 smd: 1(-3.373,1.27) 2(-3.373,-1.27) 3(3.373,-1.27) 4(3.373,1.27)
PWRPAK_SO8_DUAL
  rect 1.778x0.635 smd: 1(-3.048,1.905) 2(-3.048,0.635) 3(-3.048,-0.635) 4(-3.048,-1.905) 5(3.048,-1.905) 6(3.048,-0.635) 7(3.048,0.635) 8(3.048,1.905)
QFN24_157X157_197_NO_EP
  rect 0.711x0.305 smd: 1(-1.918,1.251) 2(-1.918,0.751) 3(-1.918,0.25) 4(-1.918,-0.25) 5(-1.918,-0.751) 6(-1.918,-1.251) 13(1.918,-1.251) 14(1.918,-0.751) 15(1.918,-0.25) 16(1.918,0.25) 17(1.918,0.751) 18(1.918,1.251)
  rect 0.305x0.711 smd: 7(-1.251,-1.918) 8(-0.751,-1.918) 9(-0.25,-1.918) 10(0.25,-1.918) 11(0.751,-1.918) 12(1.251,-1.918) 19(1.251,1.918) 20(0.751,1.918) 21(0.25,1.918) 22(-0.25,1.918) 23(-0.751,1.918) 24(-1.251,1.918)
QFN28_197X197_197_EP
  rect 1.016x0.279 smd: 1(-2.413,1.501) 2(-2.413,1.001) 3(-2.413,0.5) 4(-2.413,0) 5(-2.413,-0.5) 6(-2.413,-1.001) 7(-2.413,-1.501) 15(2.413,-1.501) 16(2.362,-1.001) 17(2.362,-0.5) 18(2.362,0) 19(2.362,0.5) 20(2.362,1.001) 21(2.362,1.501)
  rect 0.279x1.016 smd: 8(-1.501,-2.413) 9(-1.001,-2.413) 10(-0.5,-2.413) 11(0,-2.413) 12(0.5,-2.413) 13(1.001,-2.413) 14(1.501,-2.413) 22(1.501,2.413) 23(1.001,2.413) 24(0.5,2.413) 25(0,2.413) 26(-0.5,2.413) 27(-1.001,2.413) 28(-1.501,2.413)
  rect 3.048x3.048 smd: 29(0,0)
SC70
  rect 0.61x0.61 smd: 1(0.65,0.925) 2(-0.65,0.925) 3(0,-0.925)
SMB
  rect 1.905x2.286 smd: 1(-2.413,0) 2(2.413,0)
SMC
  rect 3.556x5.969 smd: 1(-3.302,0) 2(3.302,0)
SO-8
  rect 2.032x0.61 smd: 1(-2.794,1.905)
  oval 2.032x0.61 smd: 2(-2.794,0.635) 3(-2.794,-0.635) 4(-2.794,-1.905) 5(2.794,-1.905) 6(2.794,-0.635) 7(2.794,0.635) 8(2.794,1.905)
SO-8-T-PAD
  rect 2.032x0.61 smd: 1(-2.794,1.905)
  oval 2.032x0.61 smd: 2(-2.794,0.635) 3(-2.794,-0.635) 4(-2.794,-1.905) 5(2.794,-1.905) 6(2.794,-0.635) 7(2.794,0.635) 8(2.794,1.905)
  rect 2.667x3.556 smd: 9(0,0)
SOD-323
  rect 1.016x0.66 smd: 1(-1.252,0) 2(1.252,0)
SOT23
  rect 0.889x1.016 smd: 1(-1.016,-1.143) 2(1.016,-1.143) 3(0,1.143)
SOT23-5
  rect 1.143x0.61 smd: 1(-1.397,0.94)
  oval 1.143x0.61 smd: 2(-1.397,0) 3(-1.397,-0.94) 4(1.397,-0.94) 5(1.397,0.94)
SOT23-6
  rect 1.143x0.61 smd: 1(-1.397,0.94)
  oval 1.143x0.61 smd: 2(-1.397,0) 3(-1.397,-0.94) 4(1.397,-0.94) 5(1.397,0) 6(1.397,0.94)
SOT223
  rect 2.159x1.27 smd: 1(-3.162,2.413) 2(-3.162,0.114) 3(-3.162,-2.184)
  rect 2.159x3.556 smd: 4(3.073,0.114)
SOT-89
  rect 0.813x1.448 smd: 1(0,0) 2(1.499,0) 3(2.997,0)
  oval 2.083x0.711 smd: 4(1.499,3.454)
SS-01GL13
  oval 1.524x4.47 hole 0.914x3.861: 1(16.1,0) 2(0,0) 3(8.8,0)
SW3
  rect 2.159x1.067 smd: 1(0,0) 2(7.112,0)
TP6
  round 1.016 smd: 1(0,0)
TQFP100
  rect 1.651x0.274 smd: 1(-7.62,6)
  oval 1.651x0.274 smd: 2(-7.62,5.5) 3(-7.62,5) 4(-7.62,4.5) 5(-7.62,4) 6(-7.62,3.5) 7(-7.62,3) 8(-7.62,2.5) 9(-7.62,2) 10(-7.62,1.5) 11(-7.62,1) 12(-7.62,0.5) 13(-7.62,0) 14(-7.62,-0.5) 15(-7.62,-1) 16(-7.62,-1.5) 17(-7.62,-2) 18(-7.62,-2.5) 19(-7.62,-3) 20(-7.62,-3.5) 21(-7.62,-4) 22(-7.62,-4.5) 23(-7.62,-5) 24(-7.62,-5.5) 25(-7.62,-6) 51(7.62,-6) 52(7.62,-5.5) 53(7.62,-5) 54(7.62,-4.5) 55(7.62,-4) 56(7.62,-3.5) 57(7.62,-3) 58(7.62,-2.5) 59(7.62,-2) 60(7.62,-1.5) 61(7.62,-1) 62(7.62,-0.5) 63(7.62,0) 64(7.62,0.5) 65(7.62,1) 66(7.62,1.5) 67(7.62,2) 68(7.62,2.5) 69(7.62,3) 70(7.62,3.5) 71(7.62,4) 72(7.62,4.5) 73(7.62,5) 74(7.62,5.5) 75(7.62,6)
  oval 0.274x1.651 smd: 26(-6,-7.62) 27(-5.5,-7.62) 28(-5,-7.62) 29(-4.5,-7.62) 30(-4,-7.62) 31(-3.5,-7.62) 32(-3,-7.62) 33(-2.5,-7.62) 34(-2,-7.62) 35(-1.5,-7.62) 36(-1,-7.62) 37(-0.5,-7.62) 38(0,-7.62) 39(0.5,-7.62) 40(1,-7.62) 41(1.5,-7.62) 42(2,-7.62) 43(2.5,-7.62) 44(3,-7.62) 45(3.5,-7.62) 46(4,-7.62) 47(4.5,-7.62) 48(5,-7.62) 49(5.5,-7.62) 50(6,-7.62) 76(6,7.62) 77(5.5,7.62) 78(5,7.62) 79(4.5,7.62) 80(4,7.62) 81(3.5,7.62) 82(3,7.62) 83(2.5,7.62) 84(2,7.62) 85(1.5,7.62) 86(1,7.62) 87(0.5,7.62) 88(0,7.62) 89(-0.5,7.62) 90(-1,7.62) 91(-1.5,7.62) 92(-2,7.62) 93(-2.5,7.62) 94(-3,7.62) 95(-3.5,7.62) 96(-4,7.62) 97(-4.5,7.62) 98(-5,7.62) 99(-5.5,7.62) 100(-6,7.62)
TSSOP-16
  rect 1.651x0.33 smd: 1(-2.857,2.275)
  oval 1.651x0.33 smd: 2(-2.857,1.625) 3(-2.857,0.975) 4(-2.857,0.325) 5(-2.857,-0.325) 6(-2.857,-0.975) 7(-2.857,-1.625) 8(-2.857,-2.275) 9(2.857,-2.275) 10(2.857,-1.625) 11(2.857,-0.975) 12(2.857,-0.325) 13(2.857,0.325) 14(2.857,0.975) 15(2.857,1.625) 16(2.857,2.275)
USB_A_SHORT
  oval 0.914x2.54 hole 0.406x2.032: (-6.4,5.6) (6.4,5.6) 5(-6.4,0) 6(6.4,0)
  rect 1.473x1.473 hole 0.965: 1(3.5,7.35)
  round 1.473 hole 0.965: 2(1,7.35) 3(-1,7.35) 4(-3.5,7.35)

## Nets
+3V3: C3.1 C4.1 C5.1 C6.1 C12.1 C16.1 C20.1 C21.1 C24.1 C25.1 C26.1 C27.1 C28.1 C29.1 C30.1 C31.1 C38.1 C39.1 C42.1 C44.1 C45.1 C48.1 C51.1 C62.2 C71.2 C80.2 C89.2 D7.2 FB1.1 J1.1 J3.1 R1.2 R2.2 R4.1 R5.1 R11.1 R12.2 R14.1 R15.1 R28.2 R29.2 R38.2 R39.1 R54.1 R55.1 R66.1 R67.1 R79.1 R80.1 R92.1 R93.1 R105.1 R107.1 TP3.1 U1.6(VBAT) U1.11(VDD_1) U1.19(VDD_2) U1.28(VDD_3) U1.50(VDD_4) U1.75(VDD_5) U1.100(VDD_6) U2.8(VCC) U3.8(VLOGIC) U3.13(VDD) U4.16(VCC) U8.2(OUT) U8.4 U10.1 U10.2 U10.3 U10.4 U11.16(VCC) U12.1 U12.2 U12.3 U12.4 U13.16(VCC) U15.1 U15.2 U15.3 U15.4 U18.5(VCC) U20.5(V+) U21.5(VCC) U25.5(VCC) U28.5(VCC) U31.5(VCC) U34.5(VCC)
+3V6: C99.2 C100.1 C105.1 R109.2 R110.2 R111.2 R112.2 R113.2 R119.2 U37.3(OUT) U38.29(VBAT)
+5V: C40.1 C41.1 C56.2 C61.2 C65.2 C70.2 C76.2 C79.2 C83.2 C88.2 C95.2 C97.1 C98.2 C104.2 C109.2 D5.2 D9.2 D10.2 D11.2 D12.2 D13.2 D14.2 D15.2 D16.2 D18.2 D19.2 D20.2 D21.2 D23.2 D24.2 D25.2 D27.2 D28.2 D29.2 D30.2 D31.2 D33.2 D34.2 D35.2 J2.1 J6.2 J10.1 J11.3 J12.1 J13.3 J14.3 J15.1 J16.3 J17.1 J20.1 L1.1 LS1.1 Q2.2(SOURCE) R18.1 R25.1 R30.2 R35.2 R36.2 RP7.1(4) RP7.2(4) RP7.3(4) RP9.1(4) RP9.2(4) RP9.3(4) RP11.1(4) RP11.2(4) RP11.3(4) RP13.1(4) RP13.2(4) RP13.3(4) RP15.1(4) RP15.2(4) RP15.3(4) TP2.1 U5.5(IN) U8.3(VIN) U37.2(IN) U37.4(VIN) U39.6(VDD) U40.6(VDD)
+VDD_A: C13.1 C14.1 FB1.2 R10.2 U1.22(VDDA)
GND: C1.1 C2.1 C3.2 C4.2 C5.2 C6.2 C7.2 C8.2 C9.2 C10.2 C12.2 C13.2 C14.2 C15.2 C16.2 C18.2 C19.2 C20.2 C21.2 C22.2 C23.2 C24.2 C25.2 C26.2 C27.2 C28.2 C29.2 C30.2 C31.2 C32.2 C33.2 C35.2 C36.2 C37.2 C38.2 C39.2 C40.2 C41.2 C42.2 C43.2 C44.2 C45.2 C46.2 C47.2 C48.2 C49.2 C50.2 C51.2 C52.2 C53.2 C56.1 C57.1 C58.2 C59.1 C60.1 C61.1 C62.1 C65.1 C66.1 C67.2 C68.1 C69.1 C70.1 C71.1 C72.1 C73.1 C76.1 C77.2 C78.1 C79.1 C80.1 C83.1 C84.1 C85.2 C86.1 C87.1 C88.1 C89.1 C91.1 C93.2 C94.1 C95.1 C96.1 C97.2 C98.1 C99.1 C100.2 C101.2 C104.1 C106.2 C109.1 D1.1(ANODE) D2.1(A) D3.2(CATHODE) D4.1(ANODE) D5.1 D6.2(CATHODE) D7.1 D8.1(ANODE) D9.1 D10.1 D11.1 D12.1 D13.1 D14.1 D15.1 D16.1 D17.1(ANODE) D18.1 D19.1 D20.1 D21.1 D22.1(ANODE) D23.1 D24.1 D25.1 D26.1(ANODE) D27.1 D28.1 D29.1 D30.1 D31.1 D32.1(ANODE) D33.1 D34.1 D35.1 J1.5 J2.4 J3.8 J4.1 J4.3 J4.5 J4.7 J5.1 J6.3 J6.4 J8.2 J10.5 J11.1 J12.5 J13.1 J14.1 J15.5 J16.1 J17.5 J20.5 Q1.2(E) Q3.2(SOURCE) Q19.2(E) R3.1 R6.1 R9.1 R13.2 R19.2 R31.1 R33.1 R41.1 R45.1 R46.1 R48.1 R53.1 R56.1 R59.1 R61.1 R65.1 R69.1 R72.1 R74.1 R78.1 R82.1 R85.1 R87.1 R91.1 R95.1 R98.1 R100.1 R104.1 R108.1 R116.2 R122.1 RP2.5 RP2.6(5) RP2.7(5) RP2.8(5) RP4.5 RP4.6(5) RP4.7(5) RP4.8(5) RP6.5 RP6.6(5) RP6.7(5) RP6.8(5) TP4.1 U1.10(VSS_1) U1.20(VSSA) U1.27(VSS_2) U1.74(VSS_3) U1.99(VSS_4) U2.1(A0) U2.2(A1) U2.3(A2) U2.4(VSS) U2.7(WP) U3.1(CLK_IN) U3.9(AD0) U3.18(GND) U4.15(GND) U5.2(GND) U6.4(GND) U6.5(G1) U6.6(G2) U7.2(GND) U8.1(GND) U9.6(GND) U9.9(TPAD) U11.8(GND) U11.15(CLK_INH) U13.3(E) U13.4(F) U13.5(G) U13.6(H) U13.8(GND) U13.10(SA) U13.14(D) U13.15(CLK_INH) U14.3(GND) U16.2 U17.2 U18.3(GND) U19.3(GND) U20.2(V-) U21.3(GND) U23.7(GND) U23.29(TP) U25.2(GND) U26.7(GND) U26.29(TP) U28.2(GND) U29.7(GND) U29.29(TP) U31.2(GND) U32.7(GND) U32.29(TP) U34.2(GND) U35.7(GND) U35.29(TP) U37.1(GND) U38.16(GND3) U38.32(GND5) U39.7(GND) U40.7(GND)
GND_OPT: J9.4 U16.3 U17.3 U22.2
VBAT: C35.1 C36.1 C37.1 C47.1 D1.2(CATHODE) J4.2 J4.4 J4.6 J4.8 J6.1 R43.1 U9.7(VIN) U19.6(VCC) U24.2 U27.2 U30.2 U33.2 U36.2
A_OUT_1: J10.8 Q4.3(S) Q4.7(D_2) Q4.8(D2) TP19.1 U23.22(SA)
A_OUT_2: J12.8 Q7.3(S) Q7.7(D_2) Q7.8(D2) TP27.1 U26.22(SA)
A_OUT_3: J20.8 Q10.3(S) Q10.7(D_2) Q10.8(D2) TP35.1 U29.22(SA)
A_OUT_4: J15.8 Q13.3(S) Q13.7(D_2) Q13.8(D2) TP43.1 U32.22(SA)
A_OUT_5: J17.8 Q16.3(S) Q16.7(D_2) Q16.8(D2) TP51.1 U35.22(SA)
ADC_BAT_V: C52.1 R43.2 R45.2 U1.36(PB1)
ADC_CAP_V: C53.1 D7.3 R37.1 R44.2 U1.35(PB0)
B_OUT_1: J10.7 Q5.3(S) Q5.7(D_2) Q5.8(D2) TP18.1 U23.20(SB)
B_OUT_2: J12.7 Q8.3(S) Q8.7(D_2) Q8.8(D2) TP26.1 U26.20(SB)
B_OUT_3: J20.7 Q11.3(S) Q11.7(D_2) Q11.8(D2) TP34.1 U29.20(SB)
B_OUT_4: J15.7 Q14.3(S) Q14.7(D_2) Q14.8(D2) TP42.1 U32.20(SB)
B_OUT_5: J17.7 Q17.3(S) Q17.7(D_2) Q17.8(D2) TP50.1 U35.20(SB)
BLE_RX: U1.56(PD9) U38.10(TX/GPIO0)
BLE_TX: U1.55(PD8) U38.11(RX/GPIO1)
BOOT0: RP5.1(4) U1.94(BOOT0)
BOOT1: R13.1 U1.37(PB2)
BUZZER: R8.1 U1.16(PC1)
C_OUT_1: J10.6 Q6.3(S) Q6.7(D_2) Q6.8(D2) TP17.1 U23.18(SC)
C_OUT_2: J12.6 Q9.3(S) Q9.7(D_2) Q9.8(D2) TP25.1 U26.18(SC)
C_OUT_3: J20.6 Q12.3(S) Q12.7(D_2) Q12.8(D2) TP33.1 U29.18(SC)
C_OUT_4: J15.6 Q15.3(S) Q15.7(D_2) Q15.8(D2) TP41.1 U32.18(SC)
C_OUT_5: J17.6 Q18.3(S) Q18.7(D_2) Q18.8(D2) TP49.1 U35.18(SC)
CAP_V_IN: J9.2 R44.1 TP12.1
CHIP: R27.2 R31.2 U1.26(PA3) U19.4(IN_B)
CHIP_OUT: J9.1 TP11.1 U17.4 U19.5(OUT_B)
DIP_SW_CLK: U1.65(PC8) U11.2(CLK) U13.2(CLK)
DIP_SW_D: U1.66(PC9) U11.9(QH)
DIP_SW_LD: U1.64(PC7) U11.1(SF/L\D\) U13.1(SF/L\D\)
ENCODER_A_1: U1.23(PA0) U25.6(1Y)
ENCODER_A_2: U1.31(PA6) U28.6(1Y)
ENCODER_A_3: U1.92(PB6) U31.6(1Y)
ENCODER_A_4: U1.77(PA15) U34.6(1Y)
ENCODER_B_1: U1.24(PA1) U25.4(2Y)
ENCODER_B_2: U1.32(PA7) U28.4(2Y)
ENCODER_B_3: U1.93(PB7) U31.4(2Y)
ENCODER_B_4: U1.89(PB3) U34.4(2Y)
FSYNC: R3.2 U1.9(PC15) U3.11(FSYNC)
HA_A_1: D10.3 RP8.2(4) U23.1(HA+)
HA_A_2: D16.3 RP10.2(4) U26.1(HA+)
HA_A_3: D23.3 RP12.2(4) U29.1(HA+)
HA_A_4: D28.3 RP14.2(4) U32.1(HA+)
HA_A_5: D34.3 RP16.2(4) U35.1(HA+)
HA_B_1: D11.3 RP8.3(4) U23.3(HB+)
HA_B_2: D14.3 RP10.3(4) U26.3(HB+)
HA_B_3: D20.3 RP12.3(4) U29.3(HB+)
HA_B_4: D29.3 RP14.3(4) U32.3(HB+)
HA_B_5: D35.3 RP16.3(4) U35.3(HB+)
HA_C_1: D9.3 RP8.1(4) U23.5(HC+)
HA_C_2: D15.3 RP10.1(4) U26.5(HC+)
HA_C_3: D21.3 RP12.1(4) U29.5(HC+)
HA_C_4: D27.3 RP14.1(4) U32.5(HC+)
HA_C_5: D33.3 RP16.1(4) U35.5(HC+)
I2C_SCL: R1.1 U1.47(PB10) U2.6(SCL) U3.23(SCL)
I2C_SDA: R2.1 U1.48(PB11) U2.5(SDA) U3.24(SDA)
IR_BALL_DECT: R42.2 U1.15(PC0) U21.4(Y)
IR_BALL_DECT_IN: D5.3 R35.1 R40.1 U21.2(A)
IR_PWM: R32.1 U1.95(PB8)
JTAG_SWDCLK: J1.3 R6.2 U1.76(PA14)
JTAG_SWDIO: J1.2 R5.2 U1.72(PA13)
LED_CLK: R24.2 U1.30(PA5)
LED_COMM: R23.2 U1.67(PA8)
LED_DAT: R22.2 U1.91(PB5)
LED_PWR_ON: Q2.1(GATE) R25.2 U1.57(PD10)
MODE_1: RP5.2(4) U13.11(A)
MODE_2: RP5.3(4) U13.12(B)
MODE_3: RP5.4 U13.13(C)
MOTOR_BRK_1: R55.2 U1.3(PE4) U23.28(BRAKEZ)
MOTOR_BRK_2: R67.2 U1.4(PE5) U26.28(BRAKEZ)
MOTOR_BRK_3: R80.2 U1.5(PE6) U29.28(BRAKEZ)
MOTOR_BRK_4: R93.2 U1.38(PE7) U32.28(BRAKEZ)
MOTOR_BRK_5: R107.2 U1.39(PE8) U35.28(BRAKEZ)
MOTOR_DIR_1: R53.2 U1.97(PE0) U23.26(DIR)
MOTOR_DIR_2: R65.2 U1.98(PE1) U26.26(DIR)
MOTOR_DIR_3: R78.2 U1.1(PE2) U29.26(DIR)
MOTOR_DIR_4: R91.2 U1.2(PE3) U32.26(DIR)
MOTOR_DIR_5: R104.2 U1.41(PE10) U35.26(DIR)
MOTOR_PWM_1: R54.2 U1.40(PE9) U23.27(ENABLE)
MOTOR_PWM_2: R66.2 U1.42(PE11) U26.27(ENABLE)
MOTOR_PWM_3: R79.2 U1.44(PE13) U29.27(ENABLE)
MOTOR_PWM_4: R92.2 U1.45(PE14) U32.27(ENABLE)
MPU_INT: R4.2 U1.8(PC14) U3.12(INT)
MR_BALL_PWM: R105.2 U1.96(PB9) U35.27(ENABLE)
MUTE: R113.1 TP53.1 U1.33(PC4) U38.15(MUTE/GPIO5) U39.1(CTRL) U40.1(CTRL)
NEXT: R111.1 U1.61(PD14) U38.6(NEXT/TDO)
NRST: C18.1 R7.2 R11.2 TP1.1 U1.14(NRST)
NUM_1: RP3.1(4) U11.3(E)
NUM_2: RP3.2(4) U11.4(F)
NUM_3: RP3.3(4) U11.5(G)
NUM_4: RP3.4 U11.6(H)
PREV: R112.1 U1.60(PD13) U38.7(PREV/TDI)
RF_CE: J3.2 U1.83(PD2)
RF_FREQ_1: RP1.1(4) U11.11(A)
RF_FREQ_2: RP1.2(4) U11.12(B)
RF_FREQ_3: RP1.3(4) U11.13(C)
RF_FREQ_4: RP1.4 U11.14(D)
RF_IRQ: J3.7 R12.1 U1.81(PD0)
RF_SPI_NCS: J3.3 U1.82(PD1)
RS232_1_RX: J2.3 U4.13(R1IN)
RS232_1_TX: J2.2 U4.14(T1OUT)
RS232_2_RX: J6.5 U4.8(R2IN)
RS232_2_TX: J6.6 U4.7(T2OUT)
RSTN: Q19.3(C) R119.1 U1.18(PC3) U38.8(RSTN)
SHOOT: R29.1 U1.25(PA2) U18.2(B)
SHOOT_2: R26.2 U18.4(Y) U19.2(IN_A)
SHOOT_OFF: R34.2 R38.1 U1.7(PC13) U20.4(OUT)
SHOOT_OUT: J9.3 TP13.1 U16.4 U19.7(OUT_A)
SPI_MISO: J3.6 U1.79(PC11)
SPI_MOSI: J3.5 U1.80(PC12)
SPI_SCK: J3.4 U1.78(PC10)
SPK_L_N: C102.1 U38.24(AUDIO_LN)
SPK_L_P: C103.1 U38.25(AUDIO_LP)
SPK_R_N: C107.1 U38.27(AUDIO_RN)
SPK_R_P: C108.1 U38.26(AUDIO_RP)
UART1_RX: U1.69(PA10) U4.12(R1OUT)
UART1_TX: U1.68(PA9) U4.11(T1IN)
UART2_RX: U1.87(PD6) U4.9(R2OUT)
UART2_TX: U1.86(PD5) U4.10(T2IN)
USB_DM: R16.1 U1.70(PA11)
USB_DP: R17.1 U1.71(PA12)
USB_V_EN: R14.2 U1.84(PD3) U5.4(EN)
USB_VBUS: C32.1 C33.1 U5.1(OUT) U6.1(VBUS) U7.5(VCC)
VOL+: R109.1 U1.46(PE15) U38.4(VOL+/TMS)
VOL-: R110.1 U1.62(PD15) U38.5(VOL-/TCK)
N16212342: C9.1 C10.1 R10.1 U1.21(VREF+)
N16212410: U1.63(PC6)
N16212746: R16.2 U6.2(D-) U7.3(I/O2)
N16212776: R17.2 U6.3(D+) U7.1(I/O1)
N16213098: C7.1 U3.10(REGOUT)
N16213170: C8.1 U3.20(CPOUT)
N16214174: J1.4 R7.1
N16214228: R15.2 U5.3(FAULT)
N16214444: Q1.1(B) R8.2 R9.2
N16214506: LS1.2 Q1.3(C)
N16216300: C2.2 U1.13(PH1) Y1.1
N16216320: C1.2 U1.12(PH0) Y1.2
N16216718: C23.1 U1.49(VCAP_1)
N16216722: C22.1 U1.73(VCAP_2)
N16216872: H1.1 H1.2 H1.3 H1.4 H1.5 H1.6 H1.7 H1.8 H1.9
N16216974: H2.1 H2.2 H2.3 H2.4 H2.5 H2.6 H2.7 H2.8 H2.9
N16217080: H3.1 H3.2 H3.3 H3.4 H3.5 H3.6 H3.7 H3.8 H3.9
N16217240: H4.1 H4.2 H4.3 H4.4 H4.5 H4.6 H4.7 H4.8 H4.9
N16217582: C15.1 U4.2(V+)
N16217594: C19.1 U4.6(V-)
N16217668: C17.1 U4.4(C2+)
N16217676: C11.2 U4.3(C1-)
N16217680: C11.1 U4.1(C1+)
N16217684: C17.2 U4.5(C2-)
N16222454: C46.1 D4.2(CATHODE) J5.2 R28.1 TP6.1 U18.1(A)
N16222490: RP1.8(5) RP2.1(4) U10.8
N16222522: RP1.7(5) RP2.2(4) U10.7
N16222576: RP1.6(5) RP2.3(4) U10.6
N16222640: RP1.5 RP2.4 U10.5
N16223004: R20.2 R22.1 U14.1(DI)
N16223050: J7.1 R30.1 TP7.1
N16223096: C49.1 R39.2 R41.2 U20.3(-IN)
N16223154: C34.1 D2.2(K) L1.2 U9.8(PH)
N16223166: R18.2 R19.1 U9.4(VSNS)
N16223316: J7.2 Q3.3(DRAIN) TP8.1
N16223472: C34.2 U9.1(BOOT)
N16223708: R21.2 R24.1 U14.2(CI)
N16223800: C43.1 Q2.3(DRAIN) R20.1 R21.1 U14.4(VCC)
N16223854: D6.1(ANODE) R42.1
N16223890: U11.10(SA) U13.9(QH)
N16224232: R26.1 U16.1
N16224936: J9.6 U22.3
N16225198: Q3.1(GATE) R32.2 R33.2
N16225308: C50.1 J8.1 R36.1 TP9.1
N16225518: J8.3 R40.2 TP10.1
N16225732: R27.1 U17.1
N16226050: D3.1(ANODE) R23.1
N16226124: R34.1 R37.2 U20.1(+IN)
N16231004: J10.2 RP7.6(5) RP8.8(5) TP14.1
N16231012: J10.3 RP7.7(5) RP8.7(5) TP15.1
N16231068: J10.4 RP7.8(5) RP8.6(5) TP16.1
N16231202: J12.2 RP9.6(5) RP10.8(5) TP22.1
N16231224: J12.3 RP9.7(5) RP10.7(5) TP23.1
N16231228: J12.4 RP9.8(5) RP10.6(5) TP24.1
N16231344: J13.2 R70.2 TP28.1
N16231348: D19.3 R71.1 U28.3(2A)
N16231352: J13.4 R71.2 TP29.1
N16231410: C64.2 C67.1 C68.2 D17.2(CATHODE) Q7.5(D_2) Q7.6(D2) Q8.5(D_2) Q8.6(D2) Q9.5(D_2) Q9.6(D2) U26.11(VBB) U27.1
N16231448: C66.2 R62.2 U26.8(HBIAS)
N16231582: D18.3 R70.1 U28.1(1A)
N16231708: Q5.2(G) U23.15(GLB)
N16231980: C63.2 U26.9(CP1)
N16231984: C63.1 U26.10(CP2)
N16232020: R59.2 U26.25(CLD)
N16232070: R61.2 R62.1 U26.2(HA-) U26.4(HB-) U26.6(HC-)
N16232434: C64.1 U26.12(VCP)
N16232510: Q7.4(G) R60.2
N16232530: R60.1 U26.21(GHA)
N16232652: R63.1 U26.19(GHB)
N16232660: Q8.4(G) R63.2
N16232730: J11.2 R57.2 TP20.1
N16232734: D13.3 R58.1 U25.3(2A)
N16232738: J11.4 R58.2 TP21.1
N16232790: R64.1 U26.17(GHC)
N16232794: Q9.4(G) R64.2
N16232838: Q7.2(G) U26.16(GLA)
N16232850: Q8.2(G) U26.15(GLB)
N16232866: Q9.2(G) U26.14(GLC)
N16232926: Q7.1(S) Q8.1(S) Q9.1(S) R68.2 R69.2
N16233028: C69.2 R68.1 U26.13(SENSE)
N16233226: C55.2 C58.1 C59.2 D8.2(CATHODE) Q4.5(D_2) Q4.6(D2) Q5.5(D_2) Q5.6(D2) Q6.5(D_2) Q6.6(D2) U23.11(VBB) U24.1
N16233284: C57.2 R49.2 U23.8(HBIAS)
N16233424: D12.3 R57.1 U25.1(1A)
N16233882: C54.2 U23.9(CP1)
N16233886: C54.1 U23.10(CP2)
N16233926: R46.2 U23.25(CLD)
N16233960: R48.2 R49.1 U23.2(HA-) U23.4(HB-) U23.6(HC-)
N16234200: C55.1 U23.12(VCP)
N16234296: R47.1 U23.21(GHA)
N16234430: R50.1 U23.19(GHB)
N16234438: Q5.4(G) R50.2
N16234556: R51.1 U23.17(GHC)
N16234560: Q6.4(G) R51.2
N16234618: Q4.2(G) U23.16(GLA)
N16234658: Q6.2(G) U23.14(GLC)
N16234708: Q4.1(S) Q5.1(S) Q6.1(S) R52.2 R56.2
N16234816: C60.2 R52.1 U23.13(SENSE)
N16242851: J20.2 RP11.6(5) RP12.8(5) TP30.1
N16242877: J20.4 RP11.8(5) RP12.6(5) TP32.1
N16242881: J20.3 RP11.7(5) RP12.7(5) TP31.1
N16242947: J15.2 RP13.6(5) RP14.8(5) TP38.1
N16242969: J15.3 RP13.7(5) RP14.7(5) TP39.1
N16242981: J15.4 RP13.8(5) RP14.6(5) TP40.1
N16243085: D31.3 R97.1 U34.3(2A)
N16243089: J16.2 R96.2 TP44.1
N16243107: J16.4 R97.2 TP45.1
N16243155: C82.2 C85.1 C86.2 D26.2(CATHODE) Q13.5(D_2) Q13.6(D2) Q14.5(D_2) Q14.6(D2) Q15.5(D_2) Q15.6(D2) U32.11(VBB) U33.1
N16243193: C84.2 R88.2 U32.8(HBIAS)
N16243319: D30.3 R96.1 U34.1(1A)
N16243721: C81.1 U32.10(CP2)
N16243729: C81.2 U32.9(CP1)
N16243757: R85.2 U32.25(CLD)
N16243811: R87.2 R88.1 U32.2(HA-) U32.4(HB-) U32.6(HC-)
N16244015: C82.1 U32.12(VCP)
N16244099: Q13.4(G) R86.2
N16244111: R86.1 U32.21(GHA)
N16244229: Q14.4(G) R89.2
N16244237: R89.1 U32.19(GHB)
N16244299: J14.2 R83.2 TP36.1
N16244311: J14.4 R84.2 TP37.1
N16244315: D25.3 R84.1 U31.3(2A)
N16244363: R90.1 U32.17(GHC)
N16244387: Q15.4(G) R90.2
N16244447: Q13.2(G) U32.16(GLA)
N16244471: Q14.2(G) U32.15(GLB)
N16244479: Q15.2(G) U32.14(GLC)
N16244549: Q13.1(S) Q14.1(S) Q15.1(S) R94.2 R95.2
N16244649: C87.2 R94.1 U32.13(SENSE)
N16244783: C73.2 C75.2 C77.1 D22.2(CATHODE) Q10.5(D_2) Q10.6(D2) Q11.5(D_2) Q11.6(D2) Q12.5(D_2) Q12.6(D2) U29.11(VBB) U30.1
N16244821: C72.2 R75.2 U29.8(HBIAS)
N16244917: D24.3 R83.1 U31.1(1A)
N16245297: C74.1 U29.10(CP2)
N16245309: C74.2 U29.9(CP1)
N16245341: R72.2 U29.25(CLD)
N16245371: R74.2 R75.1 U29.2(HA-) U29.4(HB-) U29.6(HC-)
N16245565: C75.1 U29.12(VCP)
N16245657: R73.1 U29.21(GHA)
N16245661: Q10.4(G) R73.2
N16245779: Q11.4(G) R76.2
N16245787: R76.1 U29.19(GHB)
N16245901: Q12.4(G) R77.2
N16245905: R77.1 U29.17(GHC)
N16245981: Q10.2(G) U29.16(GLA)
N16246009: Q11.2(G) U29.15(GLB)
N16246065: Q12.2(G) U29.14(GLC)
N16246163: Q10.1(S) Q11.1(S) Q12.1(S) R81.2 R82.2
N16246325: C78.2 R81.1 U29.13(SENSE)
N16248666: J17.2 RP15.6(5) RP16.8(5) TP46.1
N16248688: J17.3 RP15.7(5) RP16.7(5) TP47.1
N16248692: J17.4 RP15.8(5) RP16.6(5) TP48.1
N16248822: C92.2 C93.1 C94.2 D32.2(CATHODE) Q16.5(D_2) Q16.6(D2) Q17.5(D_2) Q17.6(D2) Q18.5(D_2) Q18.6(D2) U35.11(VBB) U36.1
N16248876: C91.2 R101.2 U35.8(HBIAS)
N16249066: C90.2 U35.9(CP1)
N16249070: C90.1 U35.10(CP2)
N16249094: R98.2 U35.25(CLD)
N16249128: R100.2 R101.1 U35.2(HA-) U35.4(HB-) U35.6(HC-)
N16249326: C92.1 U35.12(VCP)
N16249418: Q16.4(G) R99.2
N16249422: R99.1 U35.21(GHA)
N16249556: R102.1 U35.19(GHB)
N16249564: Q17.4(G) R102.2
N16249674: R103.1 U35.17(GHC)
N16249706: Q16.2(G) U35.16(GLA)
N16249718: Q17.2(G) U35.15(GLB)
N16249734: Q18.2(G) U35.14(GLC)
N16249780: Q16.1(S) Q17.1(S) Q18.1(S) R106.2 R108.2
N16249898: C96.2 R106.1 U35.13(SENSE)
N16251307: D36.1(ANODE) R114.2
N16252156: C102.2 R117.1
N16252160: C103.2 R118.1
N16252164: R117.2 U39.3(INT-)
N16252176: R118.2 U39.4(INT+)
N16252300: C101.1 U39.2(BYPASS)
N16254339: C107.2 R121.1
N16254359: C108.2 R123.1
N16254363: R121.2 U40.3(INT-)
N16254367: R123.2 U40.4(INT+)
N16254401: C106.1 U40.2(BYPASS)
N16258530: Q19.1(B) R120.1 R122.2
N16259236: C105.2 R120.2
N16260621: FB2.1 U39.8(OUT-)
N16260625: FB3.1 U39.5(OUT+)
N16260645: FB3.2 J18.1
N16260657: FB2.2 J18.2
N16260735: FB4.1 U40.8(OUT-)
N16260742: FB5.1 U40.5(OUT+)
N16260748: FB4.2 J19.2
N16260758: FB5.2 J19.1
N16262221: D37.1(ANODE) R115.2
N16262712: R115.1 U38.13(LED0/GPIO3)
N16262719: R114.1 U38.14(LED1/GPIO4)
N16262726: D36.2(CATHODE) D37.2(CATHODE) U38.1(GND1)
N16265844: R116.1 U38.17(GND4)
N16266482: TP52.1 U38.28(VBUS)
N16284199: RP3.8(5) RP4.1(4) U12.8
N16284203: RP3.7(5) RP4.2(4) U12.7
N16284207: RP3.6(5) RP4.3(4) U12.6
N16284215: RP3.5 RP4.4 U12.5
N16285416: RP5.8(5) RP6.1(4) TP5.1 U15.8
N16285420: RP5.7(5) RP6.2(4) U15.7
N16285424: RP5.6(5) RP6.3(4) U15.6
N16285432: RP5.5 RP6.4 U15.5
N16299810: Q4.4(G) R47.2
N16305767: Q18.4(G) R103.2

Pads without a net: J9 5; RP7 4 5; RP8 4 5; RP9 4 5; RP10 4 5; RP11 4 5; RP12 4 5; RP13 4 5; RP14 4 5; RP15 4 5; RP16 4 5; U1 17 29 34 43 51 52 53 54 58 59 85 88 90; U3 2 3 4 5 6 7 14 15 16 17 19 21 22; U7 4 6; U9 2 3 5; U11 7; U13 7; U14 5 6; U19 1 8; U21 1; U22 1; U23 23 24; U26 23 24; U29 23 24; U32 23 24; U35 23 24; U38 2 3 9 12 18 19 20 21 22 23 30 31

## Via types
v1: diameter 0.61, hole 0.356, TOP to BOTTOM, 288 vias
v2: diameter 0.686, hole 0.406, TOP to BOTTOM, 868 vias
v3: diameter 1.016, hole 0.508, TOP to BOTTOM, 5 vias

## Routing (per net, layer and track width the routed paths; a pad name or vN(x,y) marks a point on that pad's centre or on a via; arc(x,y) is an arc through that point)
+3V3: length 218.6
  TOP w0.152: 97.14,59.52 97.14,57.75 ; v1(115.47,69.42) R79.1 R80.1 ; v1(67.77,28.32) 67.77,27.71 67.31,27.25 C25.1 ; v1(67.77,28.32) C26.1 ; v1(67.77,28.32) 69.23,29.78 U1.50 ; C6.1 83.06,50.8 82.72,50.46 U3.13 ; U1.19 75.26,41.48 75.9,40.84 75.96,40.84 v2(75.96,40.84) ; U28.5 v2(99.75,43.84) ; U4.16 48.91,35.07 49.89,36.04 50.45,36.04 C12.1 C16.1 ; v1(78.46,51.61) 78.46,51.59 78.73,51.32 U3.8
  TOP w0.203: C31.1 86.4,28.16 U1.75 ; C3.1 58.57,34.76 59.12,34.21 U2.8 ; U21.5 132.13,91.85 C51.1 ; R5.1 83.85,23.62 v1(84.43,23.04) ; U1.28 69.46,40.78 v1(69.19,40.51)
  TOP w0.254: R39.1 53.65,46.61 v2(52.76,47.5) ; R12.2 108.51,22.61 R15.1 106.38,22.58 R14.1 107.75,20.8 v2(107.8,20.75) ; C89.2 v2(50.27,42.55) ; v2(52.3,41.07) R38.2 53.37,41.25 U20.5 ; v1(79.53,41.94) 79.26,42.21 U1.11 ; R1.2 v2(55.15,27.46) ; v2(96.5,58.39) 97.14,57.75 U18.5 97.14,57.72 R29.2 97.14,60.9 C45.1 ; U12.1 U12.2 U12.3 U12.4 71.21,3.64 v2(71.39,3.82) ; v2(115.83,71.58) 123.9,79.65 134.34,79.65 135.66,80.98 135.66,82.19 136.91,83.44 139.75,83.44 140.35,84.04 D7.2 ; v1(84.64,41.73) 84.68,41.78 U1.100 87.32,41.78 C5.1 ; v2(26.88,68.83) 28.06,67.65 R55.1 R54.1 ; v2(57.98,3.82) 57.79,3.64 U10.4 U10.3 U10.2 U10.1 ; v2(115.8,72.69) 115.93,72.69 126.49,83.26 126.49,87.68 128.12,89.31 131.62,89.31 132.13,89.81 C51.1 ; R92.1 R93.1 v2(34.43,44.39) ; v2(48.21,46.53) 47.8,46.94 C62.2 ; U1.6 v1(81.76,42.17) ; U25.5 v2(48.49,44.73) ; v2(59.77,36.3) 59.76,36.3 C3.1 ; R2.2 v2(59.87,27.41) ; U34.5 v2(48.8,40.34) ; U21.5 v2(133.33,91.87) ; U4.16 v2(48.25,35.9) ; C16.1 v2(53.27,36.07) ; U2.8 v2(60.52,35.31) ; C20.1 v2(125.96,24.18) ; U15.1 U15.2 U15.3 U15.4 84.62,3.64 v2(84.8,3.82) ; R4.1 v2(83.64,50.62) ; R67.1 R66.1 v2(95.68,70) ; R105.1 R107.1 ; U31.5 100.51,39.29 99.95,38.74 v2(98.88,38.74) ; v2(94.85,60.25) 95.46,59.64 R28.2 96.78,59.16 97.14,59.52 ; C80.2 v2(102.26,36.88) ; C71.2 v2(100.15,41.63) ; C6.1 v2(83.72,52.35) ; C48.1 v2(50.32,43.26) ; C31.1 v2(87.38,27.71) ; C21.1 v2(127.86,25.4)
  TOP w0.305: C21.1 127.81,24.91 C20.1 122,24.91 121.82,25.1 121.82,26.09 J3.1
  POWER w0.254: v2(26.88,68.83) 26.88,68.81 28.98,66.7
  BOTTOM w0.152: v2(60.76,20.94) 60.71,21 U11.16 57.17,21 C42.1 ; v2(75.96,40.84) 75.46,41.33 C29.1
  BOTTOM w0.203: v1(69.19,40.51) 69.82,39.89 C30.1 ; R11.1 v1(78.54,38.99)
  BOTTOM w0.254: v2(71.6,64.64) 72.77,63.47 TP3.1 ; v1(84.64,41.73) 84.46,41.55 C27.1 ; v2(70.59,43.76) 71.21,43.15 FB1.1 ; C28.1 80.11,41.35 v1(79.53,41.94) ; v2(107.8,20.75) 106.94,20.75 105.51,22.17 J1.1 ; v1(81.76,42.17) 81.99,41.94 C24.1 ; U13.16 76.37,21.25 v2(76.81,21.69) ; C4.1 77.8,50.95 v1(78.46,51.61) ; C44.1 v2(84.15,20.12)
  vias: v2(70.23,63.96) v2(70.23,63.3) v2(70.28,62.64) v2(70.26,61.95) v2(70.92,63.96) v2(70.94,63.27) v2(70.94,62.59) v2(70.94,61.9) v2(71.6,63.93) v2(71.63,63.25) v2(71.63,62.56) v2(71.63,61.87)
+3V6: length 34.2
  TOP w0.152: U38.29 32.86,11.62 v1(33.36,11.12)
  TOP w0.254: U38.29 25.87,11.51 C99.2 20.78,11.68 C100.1 21.03,13.64 U37.3
  BOTTOM w0.152: C105.1 R113.2 34.6,23.19 35.26,22.52 35.26,17.89 R119.2 R112.2 R111.2 R110.2 R109.2 v1(33.36,11.12)
